(* Logix 5000 project; controller Test vendor 1 type 14 code 92 rev 33.11; software revision 33.00 *)

TASK MainTask (continuous, watchdog 500 ms) : MainProgram

MODULES
   Local : vendor 1 type 14 code 92 (ICP 0, rev 33.11)
      IN : vendor 1 type 7 code 1 (ICP 3, rev 3.2, Input RPI 20 ms)
      O : vendor 1 type 7 code 15 (ICP 2, rev 3.2, Output RPI 20 ms)
      Ethernet : 1756-ENBT (ICP 1, Ethernet 192.168.0.98, rev 6.4)
         DXM : DXM (Ethernet 192.168.0.1, rev 2.22, StandardDataDriven RPI 20 ms)
END_MODULES

TYPE Banner_IOL_Port_v4 :   // UDT that has all of the data items necessary to communicate with a specific Port on a IO-Link Master
STRUCT
   Port_Controlled : INT;   // Each bit represents a port on an IO-Link Master. Set to 1 to tell AOI to control that port.
   Port_Activate : INT;   // Each bit represents a port on an IO-Link Master. When ON that port will process any commands in queue.
   Port_Read : INT;   // Each bit represents a port on an IO-Link Master. Used to determine when device AOI has requested a Read command.
   Port_Write : INT;   // Each bit represents a port on an IO-Link Master. Used to determine when device AOI has requested a Write command.
   Port_RW_Complete : INT;   // Each bit represents a port on an IO-Link Master. Tells device AOI that Read or Write request has been completed.
   Port_Device_Read : INT;
   Data_Transfer : SINT[190];   // Array to transfer data from IO-Master to device AOIs.
END_STRUCT
END_TYPE

TYPE Banner_IOLM_EL_v4 :   // Error Log for Messages to IOLM.
STRUCT
   RW : SINT;   // 0 = Read, 1 = Write.
   Port : SINT;   // Port number that generated error.
   Index : INT;   // IO-Link Index for generated error.
END_STRUCT
END_TYPE

TYPE Banner_IOLM_v4 :   // UDT to control IO-Link Masters.
STRUCT
   Message_Source_Data : SINT[190];
   Message_Destination_Data : SINT[190];
   Error_Log : Banner_IOLM_EL_v4[10];
   Error_Write_Retry : BOOL;
   Num_Error_MSGS : DINT;
   IO_Link_Master_Busy : BOOL;   // 0 = While waiting for a command, 1 = Processing command
   AOI_Reset : BOOL;
   Port_Data : Banner_IOL_Port_v4;   // All of the necessary data to work with the various ports of the IO-Link Master.
   Halt_Operation : BOOL;   // When parameter is 1 the AOI is halted as next available time frame.
   AOI_Halted : BOOL;   // AOI is in standby mode until Halt Operation tag is set back to 0.
END_STRUCT
END_TYPE

TYPE Banner_WLF_LC25C_PDIO_v4 :   // Process data for a Banner WLS Pro unit. This includes four process data types.
STRUCT
   Segment_Mode : SINT[11];   // 0 = Off, 1 = On, 2 = Flash, 3 = Animation.
   Run_Mode : Banner_WLS_CC_v4;   // Tags for Run Mode control
   Level_Mode : INT;   // Value describing level of the device range. See Level Mode Parameter for more information.
   Dim_Blend_Mode : INT;   // Value describing the amount of blend between colors selected in Dim and Blend Mode parameter data.
   Gauge_Mode_Value : INT;   // Value describing the position of the main animation.
   LED_Mode : SINT[65];   // 0 = Off, 1 = Green, 2 = Red, 3 = Orange, 4 = Amber, 5 = Yellow, 6 = Lime Green, 7 = Spring Green, 8 = Cyan, 9 = Sky Blue, 10 = Blue, 11 = Violet, 12 = Magneta, 13 = Rose, 14 = Daylight White, 15 = Custom 1.
   Transfer_Data : SINT[32];   // Data array to send the correct state of the process data output to the IO-Link master.
END_STRUCT
END_TYPE

TYPE Banner_WLS_CC_v4 :   // Tags to control color for a WLS Pro
STRUCT
   Animation : SINT;   // 0 = Off, 1 = Steady, 2 = Flash, 3 = 2 Color Flash, 4 = 2 Color Shift, 5 = Ends Steady, 6 = Ends Flash, 7 = Scroll, 8 = Center Bounce, 9 = Bounce, 10 = Center Bounce, 11 = Intensity Sweep, 12 = 2 Color Sweep, 13 = Spectrum. WLS15 Only 14 = Level Steady, 15 = Level Flash.
   Color_1 : SINT;   // 0 = Green, 1 = Red, 2 = Orange, 3 = Amber, 4 = Yellow, 5 = Lime Green, 6 = Spring Green, 7 = Cyan, 8 = Sky Blue, 9 = Blue, 10 = Violet, 11 = Magneta, 12 = Rose, 13 = Daylight White, 14 = Custom 1, 15 = Custom 2, 16 = Incandescent, 17 = Warm White, 18 = Flourescent, 19 = Neutral White, 20 = Cool White.
   Color_1_Intensity : SINT;   // 0 = High, 1 = Low, 2 = Medium, 3 = Off, 4 = Custom.
   Speed : SINT;   // 0 = Medium, 1 = Fast, 2 = Slow, 3 = Custom.
   Pulse_Pattern : SINT;   // 0 = Normal, 1 = Strobe, 2 = Three Pulse, 3 = SOS, 4 = Random.
   Color_2 : SINT;   // 0 = Green, 1 = Red, 2 = Orange, 3 = Amber, 4 = Yellow, 5 = Lime Green, 6 = Spring Green, 7 = Cyan, 8 = Sky Blue, 9 = Blue, 10 = Violet, 11 = Magneta, 12 = Rose, 13 = Daylight White, 14 = Custom 1, 15 = Custom 2, 16 = Incandescent, 17 = Warm White, 18 = Flourescent, 19 = Neutral White, 20 = Cool White.
   Color_2_Intensity : SINT;   // 0 = High, 1 = Low, 2 = Medium, 3 = Off, 4 = Custom.
   ScrollBounce : SINT;   // 0 = Solid, 1 = Blended Tail, 2 = Center Blended.
   Percent_Width_C1 : SINT;   // 1 to 100% of Color 1.
   Direction : SINT;   // 0 = Forward, 1 = Backward.
END_STRUCT
END_TYPE

TYPE Banner_WLS_DB_Config_v4 :   // Dim and Blend Mode Config.
STRUCT
   Num_of_Colors : SINT;   // 0 = 1 Color, 1 = 2 Colors, 2 = 3 colors. Number of colors to blend in variable color mode.
   Full_Scale : INT;   // 0 to 100 = Threshold Percent
   Color_1 : SINT;   // 0 = Green, 1 = Red, 2 = Orange, 3 = Amber, 4 = Yellow, 5 = Lime Green, 6 = Spring Green, 7 = Cyan, 8 = Sky Blue, 9 = Blue, 10 = Violet, 11 = Magneta, 12 = Rose, 13 = Daylight White, 14 = Custom 1, 15 = Custom 2, 16 = Incandescent, 17 = Warm White, 18 = Flourescent, 19 = Neutral White, 20 = Cool White.
   Color_1_Intensity : SINT;   // 0 = High, 1 = Low, 2 = Medium, 3 = Off, 4 = Custom
   Color_2 : SINT;   // 0 = Green, 1 = Red, 2 = Orange, 3 = Amber, 4 = Yellow, 5 = Lime Green, 6 = Spring Green, 7 = Cyan, 8 = Sky Blue, 9 = Blue, 10 = Violet, 11 = Magneta, 12 = Rose, 13 = Daylight White, 14 = Custom 1, 15 = Custom 2, 16 = Incandescent, 17 = Warm White, 18 = Flourescent, 19 = Neutral White, 20 = Cool White.
   Color_2_Intensity : SINT;   // 0 = High, 1 = Low, 2 = Medium, 3 = Off, 4 = Custom
   Color_3 : SINT;   // 0 = Green, 1 = Red, 2 = Orange, 3 = Amber, 4 = Yellow, 5 = Lime Green, 6 = Spring Green, 7 = Cyan, 8 = Sky Blue, 9 = Blue, 10 = Violet, 11 = Magneta, 12 = Rose, 13 = Daylight White, 14 = Custom 1, 15 = Custom 2, 16 = Incandescent, 17 = Warm White, 18 = Flourescent, 19 = Neutral White, 20 = Cool White.
   Color_3_Intensity : SINT;   // 0 = High, 1 = Low, 2 = Medium, 3 = Off, 4 = Custom
   Filtering : SINT;   // 0 = None, 1 = Low, 2 = Medium, 3 = High
END_STRUCT
END_TYPE

TYPE Banner_WLS_Gauge_CC_v4 :   // Parameter Data Tags for Gauge mode color control.
STRUCT
   Threshold_Enable : SINT;   // 0 = Disabled, 1 = Enabled.
   Threshold_Value_Percent : SINT;   // 0 to 100 - Threshold %
   Threshold_Comparison : SINT;   // 0 = Less than or equal to, 1 = Greater than or equal to.
   Percent_Width_of_Main_Segment : SINT;   // 0 to 100 = Percent width of color 1
   Main_CC : Banner_WLS_CC_v4;   // Color Control for the Main Lighting.
   Back_CC : Banner_WLS_CC_v4;   // Color Control for the Background Lighting.
END_STRUCT
END_TYPE

TYPE Banner_WLS_Gauge_Config_v4 :   // Tags that control Gauge Mode.
STRUCT
   Full_Scale_Value : INT;   // 0 to 100 = Threshold Percent.
   Filtering : SINT;   // 0 = None, 1 = Low, 2 = Medium, 3 = High
   Hysteresis : SINT;   // 0 = None, 1 = Low, 2 = Medium, 3 = High
   Threshold_Markers_Type : SINT;   // 0 = Off, 1= Non-Dominant, 2= Dominant.
   CC : Banner_WLS_Gauge_CC_v4[3];   // Gauge Color Control tags.
END_STRUCT
END_TYPE

TYPE Banner_WLS_Level_Config_v4 :   // Variables that Control the Level Mode of the WLS Pro.
STRUCT
   Background_Color : SINT;   // 0 = Green, 1 = Red, 2 = Orange, 3 = Amber, 4 = Yellow, 5 = Lime Green, 6 = Spring Green, 7 = Cyan, 8 = Sky Blue, 9 = Blue, 10 = Violet, 11 = Magneta, 12 = Rose, 13 = Daylight White, 14 = Custom 1, 15 = Custom 2, 16 = Incandescent, 17 = Warm White, 18 = Flourescent, 19 = Neutral White, 20 = Cool White.
   Background_Intensity : SINT;   // 0 = High, 1 = Low, 2 = Medium, 3 = Off, 4 = Custom
   Dominance : SINT;   // 0 = Non-Dominant, 1 = Dominant
   SubSegment_Style : SINT;   // 0 = Solid, 1 = Analog
   Filtering : SINT;   // 0 = None, 1 = Low, 2 = Medium, 3 = High
   Hysteresis : SINT;   // 0 = None, 1 = Low, 2 = Medium, 3 = High
   Full_Scale_Value : INT;   // Value that controls what the full scale value is
   Threshold_Marks_Type : SINT;   // WLS15 or WLF only. 0 = Off, 1 = Non-Dominant, 2 = Dominant.
   LB_Config : Banner_WLS_CC_v4;   // Level Base Configuration
   LT_Config : Banner_WLS_LT_v4[5];   // Level Threshold Configuration
END_STRUCT
END_TYPE

TYPE Banner_WLS_LT_v4 :   // Variables to configure the Level Threshold.
STRUCT
   Threshold_Enable : SINT;   // 0 = Threshold Disabled, 1 = Threshold Enabled
   Threshold_Value : SINT;   // 0 to 100 Threshold Percent
   Threshold_Comparison : SINT;   // 0 = Less than or equal to, 1 = Greater than or equal to
   Threshold_Override : SINT;   // 0 = Override not enabled, 1 = Override enabled
   Light_Control : Banner_WLS_CC_v4;   // Color Control
END_STRUCT
END_TYPE

TYPE Banner_WLS_RD_v4 :   // UDT that stores the Read Data for a WLS Pro.
STRUCT
   Master_Cycle_Time : INT;
   Min_Cycle_Time : INT;
   M_Sequence_Capability : INT;
   IO_Link_Version_ID : INT;
   Process_Data_Input_Length : INT;
   Process_Data_Output_Length : INT;
   Combined_Vendor_ID : DINT;   // IO-Link Vendor ID
   Vendor_ID1 : INT;
   Vendor_ID2 : INT;
   Combined_Device_ID : DINT;   // IO-Link Device ID
   Device_ID1 : INT;
   Device_ID2 : INT;
   Device_ID3 : INT;
   Serial_Number : STRING;
END_STRUCT
END_TYPE

TYPE Banner_WLS_Seg_Config_v4 :   // UDT for segment setup in index 66 of the parameter data.
STRUCT
   Basic_Color : SINT;   // 0 = Green, 1 = Red, 2 = Orange, 3 = Amber, 4 = Yellow, 5 = Lime Green, 6 = Spring Green, 7 = Cyan, 8 = Sky Blue, 9 = Blue, 10 = Violet, 11 = Magneta, 12 = Rose, 13 = Daylight White, 14 = Custom 1, 15 = Custom 2, 16 = Incandescent, 17 = Warm White, 18 = Flourescent, 19 = Neutral White, 20 = Cool White.
   Basic_Flash_Rate : SINT;   // 0 = Medium, 1 = Fast, 2 = Slow, 3 = Custom.
   CC : Banner_WLS_CC_v4;   // Color Control
   Manual_Segment_Offset : SINT;   // 0 to 64 = Manual Offset in LEDs.
   Manual_Segment_Width : SINT;   // 0 to 64 = Manual width in LEDs.
END_STRUCT
END_TYPE

TYPE Banner_WLS_v4 :   // All of the parameters for a WLS Pro.
STRUCT
   Initial_Global_Read : BOOL;   // Determines if all of the IO-Link data has been read into the PLC yet
   Command : INT;   // Value placed in here will activate a read or write to a specifc IO-Link Index
   Read : Banner_WLS_RD_v4;   // Read Only Data
   Write : Banner_WLS_WD_v4;   // Write Data
   Archive : Banner_WLS_WD_v4;   // Archive of the Write Data
   Reset : BOOL;   // Resets AOI. This will force a complete parameter read of the sensor.
END_STRUCT
END_TYPE

TYPE Banner_WLS_WD_v4 :   // UDT that stores the Write Data for a WLS Pro.
STRUCT
   System_Command : INT;   // See IODD file for list of commands that can be activated via the System Command interface
   Parameter_Access_Lock : SINT;   // Write access to all parameters is prohibited while value is 1. Only this parameter can be adjusted when value is 1.
   Data_Storage_Lock : SINT;   // Automatic data storage is disabled when this value is equal to 1. Read access is not affected.
   Local_Parameterization_Lock : SINT;   // Parameterization via local control elements on device is disabled.
   Local_User_Interface_Lock : SINT;   // Operation of local user interface is disabled.
   Operating_Mode_Selection : SINT;   // 0 = Segment, 1 = Run, 2 = Level, 3 = Dim & Blend, 4 = Gauge, 5 = LED
   Segment_Mode : SINT;   // 0 = Manual Segment Config. 1 trough 10 = Number of segments in Segment Mode.
   BackGround_Color : SINT;   // 0 = Green, 1 = Red, 2 = Orange, 3 = Amber, 4 = Yellow, 5 = Lime Green, 6 = Spring Green, 7 = Cyan, 8 = Sky Blue, 9 = Blue, 10 = Violet, 11 = Magneta, 12 = Rose, 13 = Daylight White, 14 = Custom 1, 15 = Custom 2, 16 = Incandescent, 17 = Warm White, 18 = Flourescent, 19 = Neutral White, 20 = Cool White.
   Background_Intensity : SINT;   // 0 = High, 1 = Low, 2 = Medium, 3 = Off, 4 = Custom
   Animation_Sync : SINT;   // 0 = Instant Update, 1 = Synchronized Update.
   SM_Config : Banner_WLS_Seg_Config_v4[11];   // Segement Mode Configuration
   LM_Config : Banner_WLS_Level_Config_v4;   // Level Mode Configuration
   Custom_Color_1_R : INT;   // 0 to 255 for Red Custom Color 1.
   Custom_Color_1_G : INT;   // 0 to 255 for Green Custom Color 1.
   Custom_Color_1_B : INT;   // 0 to 255 for Blue Custom Color 1.
   Custom_Color_2_R : INT;   // 0 to 255 for Red Custom Color 2.
   Custom_Color_2_G : INT;   // 0 to 255 for Green Custom Color 2.
   Custom_Color_2_B : INT;   // 0 to 255 for Blue Custom Color 2.
   LED_Mode_Intensity : SINT;   // 0 = High, 1 = Low, 2 = Medium, 3 = Off, 4 = Custom
   Orientation : SINT;   // 0 = Standard, 1 = Upside Down
   Custom_Intensity : SINT;   // 0 to 100 %
   Custom_Frequency : SINT;   // 0 to 255Hz
   DB_Config : Banner_WLS_DB_Config_v4;   // Dim and Blend Configuration
   G_Config : Banner_WLS_Gauge_Config_v4;   // Gauge Configuration
   Number_of_LEDs : INT;
END_STRUCT
END_TYPE

ADD_ON_INSTRUCTION Banner_DXMR90_IOLM_v4   (* revision 4.1, vendor Banner Engineering *)
// AOI that controls a Banner IO-Link Master with Banner devices.
// Revision note:
// Revised operational order for ISDU write.
VAR_IN_OUT
   IOLM : Banner_IOLM_v4; {required}
END_VAR
VAR
   Lock : DINT; {access None}
   Byte_Length : SINT; {access None}
   Current_Port : INT; {access None}   // Current port to communicate with via the IO-Link Master.
   Timer : TIMER := (PRE := 500); {access None}
   Error_Index : DINT; {access None}
   Timer2 : TIMER := (PRE := 5000); {access None}
   Temp_Index : INT; {access None}
   ErrCount : DINT; {access None}
   Timer4 : TIMER := (PRE := 2000); {access None}
   Timer5 : TIMER := (PRE := 2000); {access None}
   Timer3 : TIMER := (PRE := 2000); {access None}
   Timer6 : TIMER := (PRE := 3000); {access None}
   Timer7 : TIMER := (PRE := 3000); {access None}
END_VAR

ROUTINE Logic   (* ladder *)
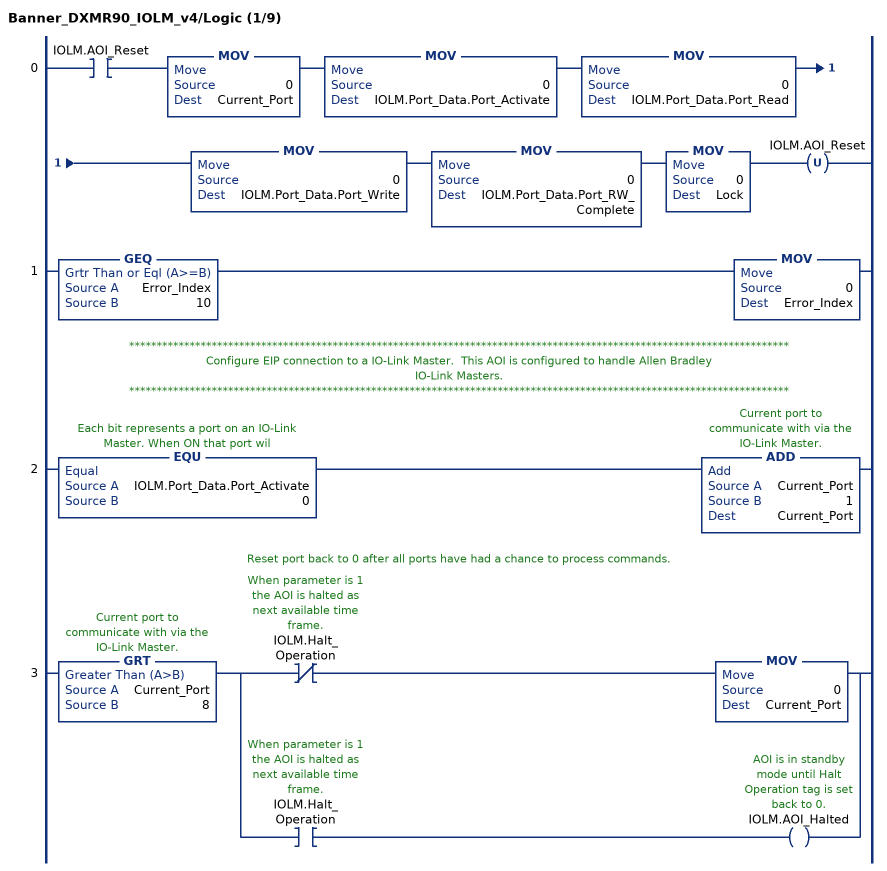
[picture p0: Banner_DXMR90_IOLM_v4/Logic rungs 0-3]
   0: XIC(IOLM.AOI_Reset)MOV(0,Current_Port)MOV(0,IOLM.Port_Data.Port_Activate)MOV(0,IOLM.Port_Data.Port_Read)MOV(0,IOLM.Port_Data.Port_Write)MOV(0,IOLM.Port_Data.Port_RW_Complete)MOV(0,Lock)OTU(IOLM.AOI_Reset);
   1: GEQ(Error_Index,10)MOV(0,Error_Index);
   // ************************************************************************************************************************
   // Configure EIP connection to a IO-Link Master.  This AOI is configured to handle Allen Bradley
   // IO-Link Masters.
   // ************************************************************************************************************************
   2: EQU(IOLM.Port_Data.Port_Activate,0)ADD(Current_Port,1,Current_Port);
   // Reset port back to 0 after all ports have had a chance to process commands.
   3: GRT(Current_Port,8)[XIO(IOLM.Halt_Operation) MOV(0,Current_Port) ,XIC(IOLM.Halt_Operation) OTE(IOLM.AOI_Halted) ];
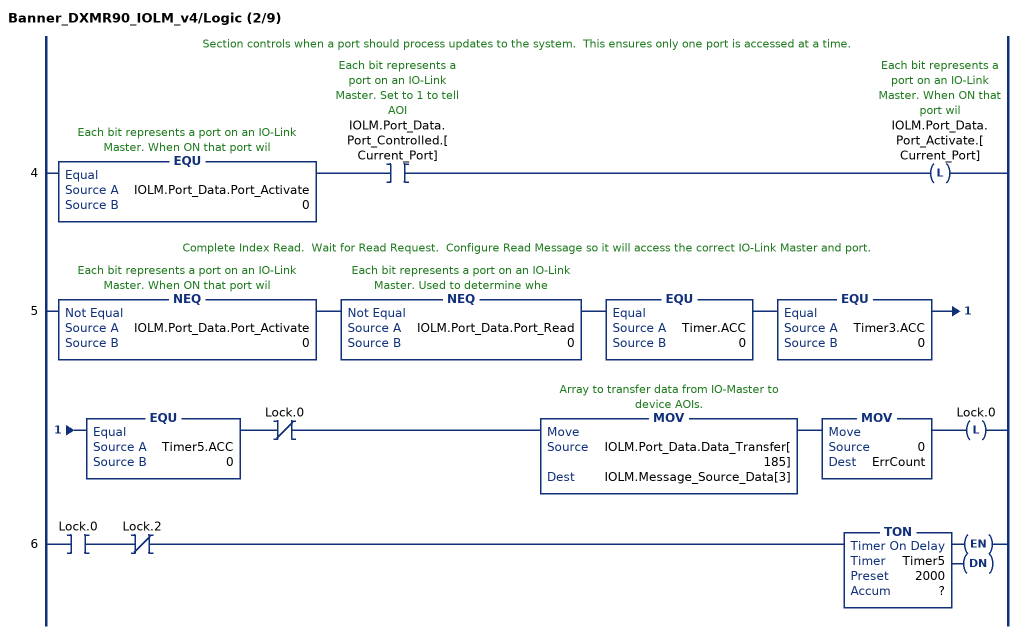
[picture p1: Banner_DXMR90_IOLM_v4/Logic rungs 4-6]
   // Section controls when a port should process updates to the system.  This ensures only one port is accessed at a time.
   4: EQU(IOLM.Port_Data.Port_Activate,0)XIC(IOLM.Port_Data.Port_Controlled.[Current_Port])OTL(IOLM.Port_Data.Port_Activate.[Current_Port]);
   // Complete Index Read.  Wait for Read Request.  Configure Read Message so it will access the correct IO-Link Master and port.
   5: NEQ(IOLM.Port_Data.Port_Activate,0)NEQ(IOLM.Port_Data.Port_Read,0)EQU(Timer.ACC,0)EQU(Timer3.ACC,0)EQU(Timer5.ACC,0)XIO(Lock.0)MOV(IOLM.Port_Data.Data_Transfer[185],IOLM.Message_Source_Data[3])MOV(0,ErrCount)OTL(Lock.0);
   6: XIC(Lock.0)XIO(Lock.2)TON(Timer5,?,?);
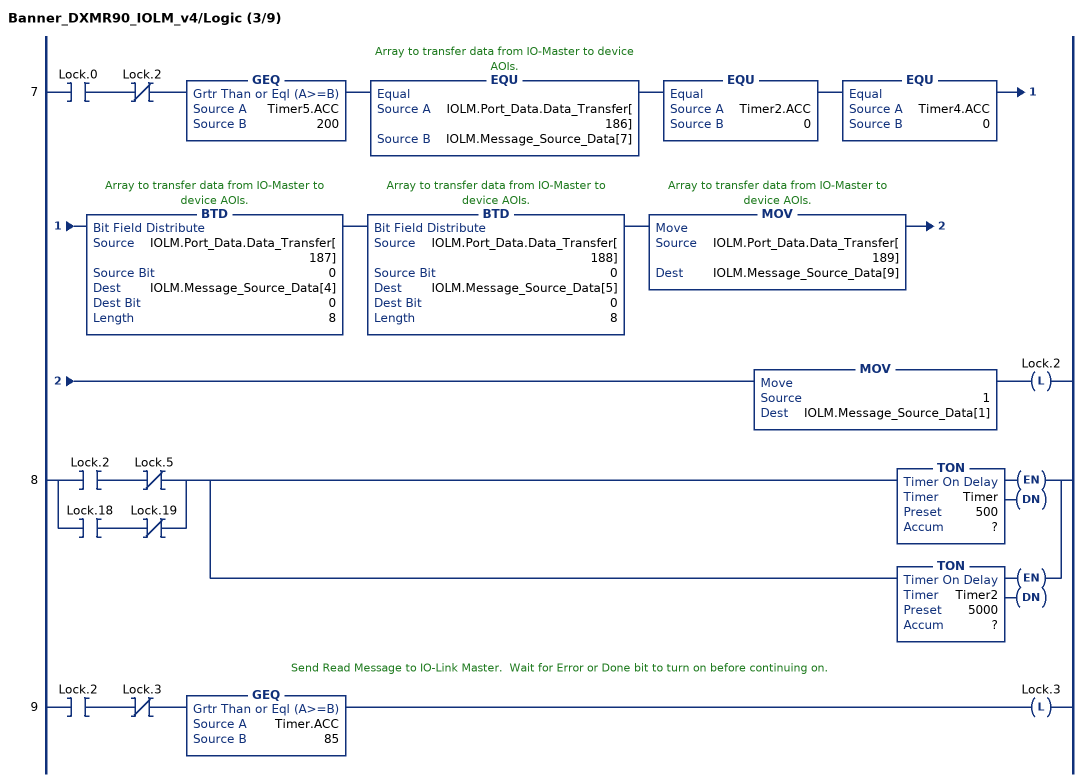
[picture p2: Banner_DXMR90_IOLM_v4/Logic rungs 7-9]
   7: XIC(Lock.0)XIO(Lock.2)GEQ(Timer5.ACC,200)EQU(IOLM.Port_Data.Data_Transfer[186],IOLM.Message_Source_Data[7])EQU(Timer2.ACC,0)EQU(Timer4.ACC,0)BTD(IOLM.Port_Data.Data_Transfer[187],0,IOLM.Message_Source_Data[4],0,8)BTD(IOLM.Port_Data.Data_Transfer[188],0,IOLM.Message_Source_Data[5],0,8)MOV(IOLM.Port_Data.Data_Transfer[189],IOLM.Message_Source_Data[9])MOV(1,IOLM.Message_Source_Data[1])OTL(Lock.2);
   8: [XIC(Lock.2) XIO(Lock.5) ,XIC(Lock.18) XIO(Lock.19) ][TON(Timer,?,?) ,TON(Timer2,?,?) ];
   // Send Read Message to IO-Link Master.  Wait for Error or Done bit to turn on before continuing on.
   9: XIC(Lock.2)XIO(Lock.3)GEQ(Timer.ACC,85)OTL(Lock.3);
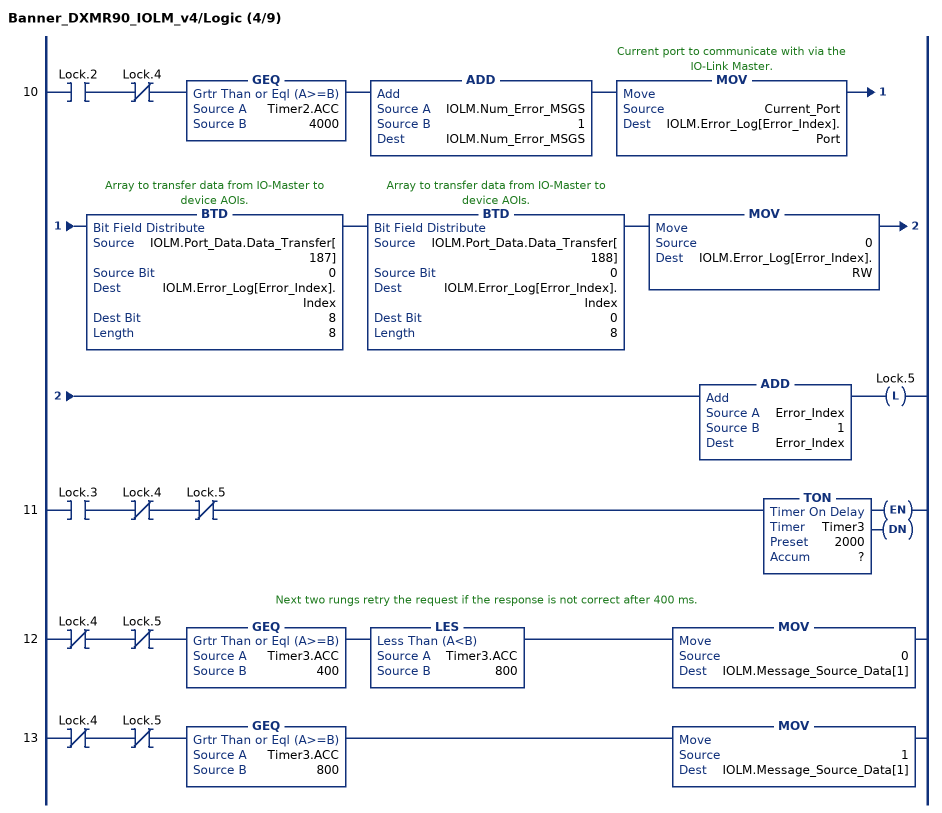
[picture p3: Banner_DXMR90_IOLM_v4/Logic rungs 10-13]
   10: XIC(Lock.2)XIO(Lock.4)GEQ(Timer2.ACC,4000)ADD(IOLM.Num_Error_MSGS,1,IOLM.Num_Error_MSGS)MOV(Current_Port,IOLM.Error_Log[Error_Index].Port)BTD(IOLM.Port_Data.Data_Transfer[187],0,IOLM.Error_Log[Error_Index].Index,8,8)BTD(IOLM.Port_Data.Data_Transfer[188],0,IOLM.Error_Log[Error_Index].Index,0,8)MOV(0,IOLM.Error_Log[Error_Index].RW)ADD(Error_Index,1,Error_Index)OTL(Lock.5);
   11: XIC(Lock.3)XIO(Lock.4)XIO(Lock.5)TON(Timer3,?,?);
   // Next two rungs retry the request if the response is not correct after 400 ms.
   12: XIO(Lock.4)XIO(Lock.5)GEQ(Timer3.ACC,400)LES(Timer3.ACC,800)MOV(0,IOLM.Message_Source_Data[1]);
   13: XIO(Lock.4)XIO(Lock.5)GEQ(Timer3.ACC,800)MOV(1,IOLM.Message_Source_Data[1]);
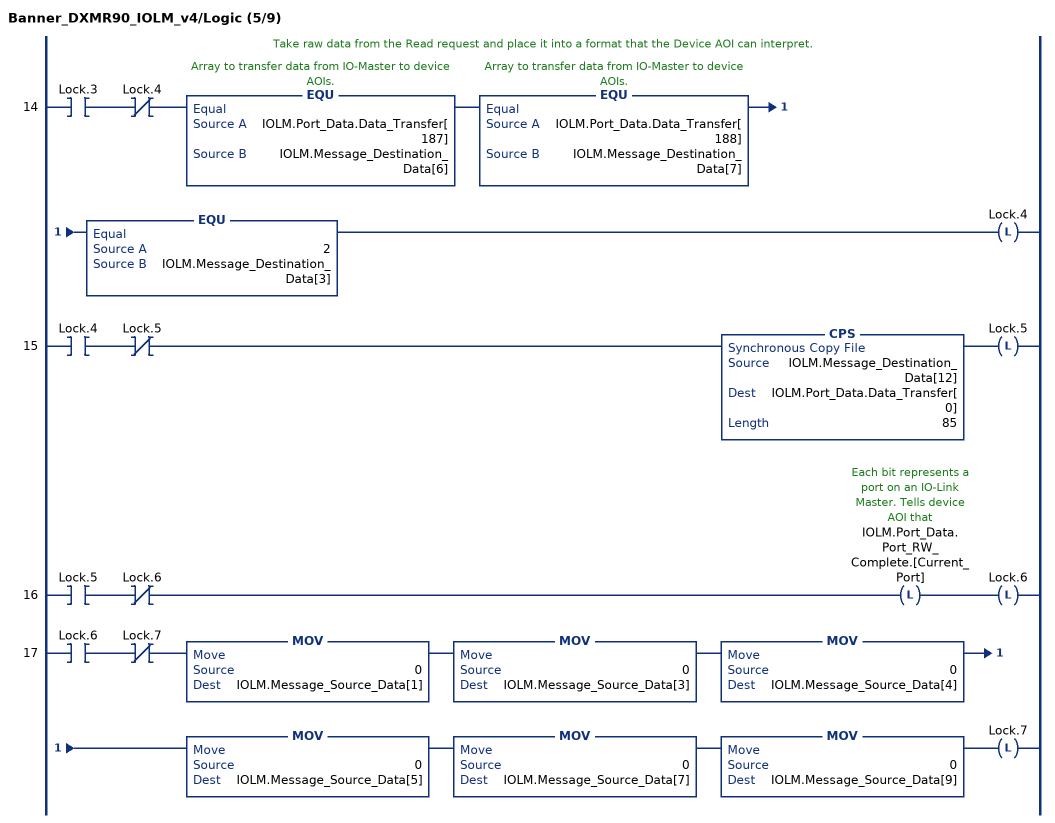
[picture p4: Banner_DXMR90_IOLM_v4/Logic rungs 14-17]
   // Take raw data from the Read request and place it into a format that the Device AOI can interpret.
   14: XIC(Lock.3)XIO(Lock.4)EQU(IOLM.Port_Data.Data_Transfer[187],IOLM.Message_Destination_Data[6])EQU(IOLM.Port_Data.Data_Transfer[188],IOLM.Message_Destination_Data[7])EQU(2,IOLM.Message_Destination_Data[3])OTL(Lock.4);
   15: XIC(Lock.4)XIO(Lock.5)CPS(IOLM.Message_Destination_Data[12],IOLM.Port_Data.Data_Transfer[0],85)OTL(Lock.5);
   16: XIC(Lock.5)XIO(Lock.6)OTL(IOLM.Port_Data.Port_RW_Complete.[Current_Port])OTL(Lock.6);
   17: XIC(Lock.6)XIO(Lock.7)MOV(0,IOLM.Message_Source_Data[1])MOV(0,IOLM.Message_Source_Data[3])MOV(0,IOLM.Message_Source_Data[4])MOV(0,IOLM.Message_Source_Data[5])MOV(0,IOLM.Message_Source_Data[7])MOV(0,IOLM.Message_Source_Data[9])OTL(Lock.7);
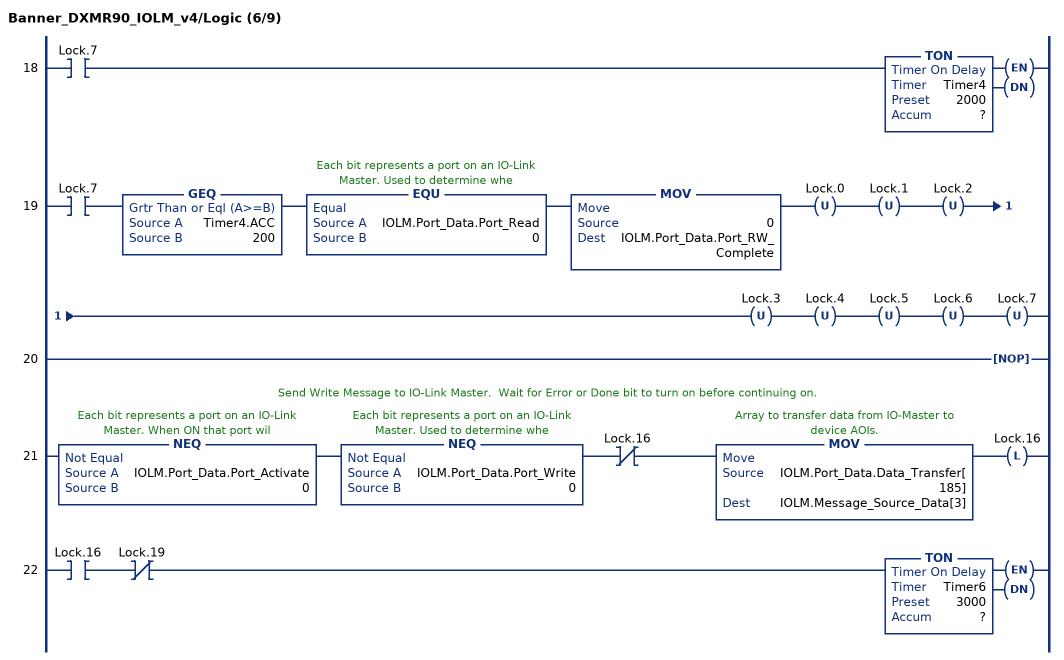
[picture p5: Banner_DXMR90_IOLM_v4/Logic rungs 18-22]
   18: XIC(Lock.7)TON(Timer4,?,?);
   19: XIC(Lock.7)GEQ(Timer4.ACC,200)EQU(IOLM.Port_Data.Port_Read,0)MOV(0,IOLM.Port_Data.Port_RW_Complete)OTU(Lock.0)OTU(Lock.1)OTU(Lock.2)OTU(Lock.3)OTU(Lock.4)OTU(Lock.5)OTU(Lock.6)OTU(Lock.7);
   20: NOP();
   // Send Write Message to IO-Link Master.  Wait for Error or Done bit to turn on before continuing on.
   21: NEQ(IOLM.Port_Data.Port_Activate,0)NEQ(IOLM.Port_Data.Port_Write,0)XIO(Lock.16)MOV(IOLM.Port_Data.Data_Transfer[185],IOLM.Message_Source_Data[3])OTL(Lock.16);
   22: XIC(Lock.16)XIO(Lock.19)TON(Timer6,?,?);
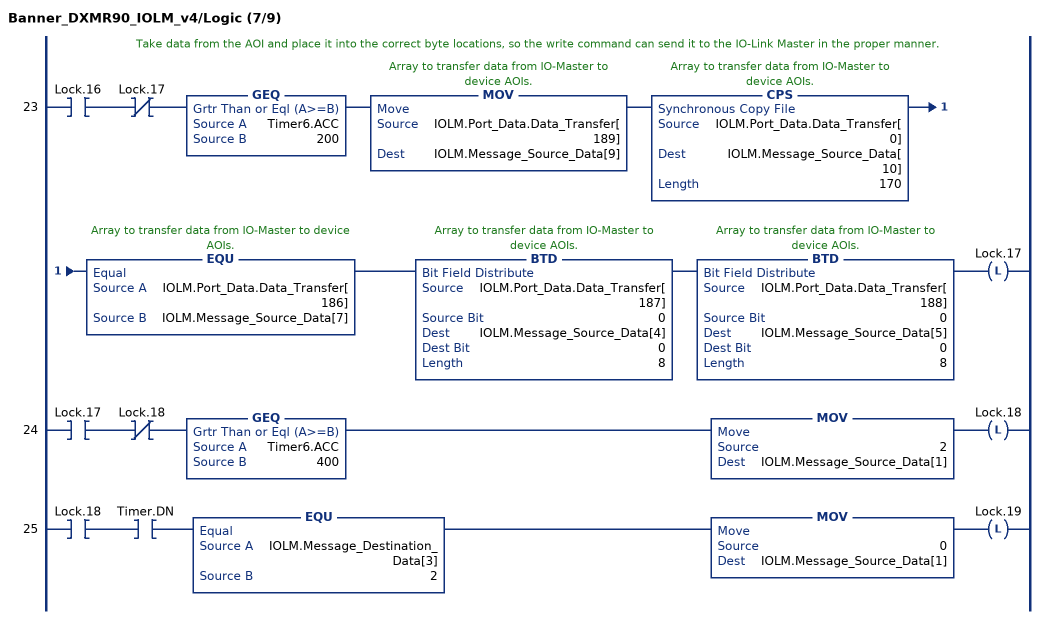
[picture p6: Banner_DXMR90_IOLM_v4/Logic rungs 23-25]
   // Take data from the AOI and place it into the correct byte locations, so the write command can send it to the IO-Link Master in the proper manner.
   23: XIC(Lock.16)XIO(Lock.17)GEQ(Timer6.ACC,200)MOV(IOLM.Port_Data.Data_Transfer[189],IOLM.Message_Source_Data[9])CPS(IOLM.Port_Data.Data_Transfer[0],IOLM.Message_Source_Data[10],170)EQU(IOLM.Port_Data.Data_Transfer[186],IOLM.Message_Source_Data[7])BTD(IOLM.Port_Data.Data_Transfer[187],0,IOLM.Message_Source_Data[4],0,8)BTD(IOLM.Port_Data.Data_Transfer[188],0,IOLM.Message_Source_Data[5],0,8)OTL(Lock.17);
   24: XIC(Lock.17)XIO(Lock.18)GEQ(Timer6.ACC,400)MOV(2,IOLM.Message_Source_Data[1])OTL(Lock.18);
   25: XIC(Lock.18)XIC(Timer.DN)EQU(IOLM.Message_Destination_Data[3],2)MOV(0,IOLM.Message_Source_Data[1])OTL(Lock.19);
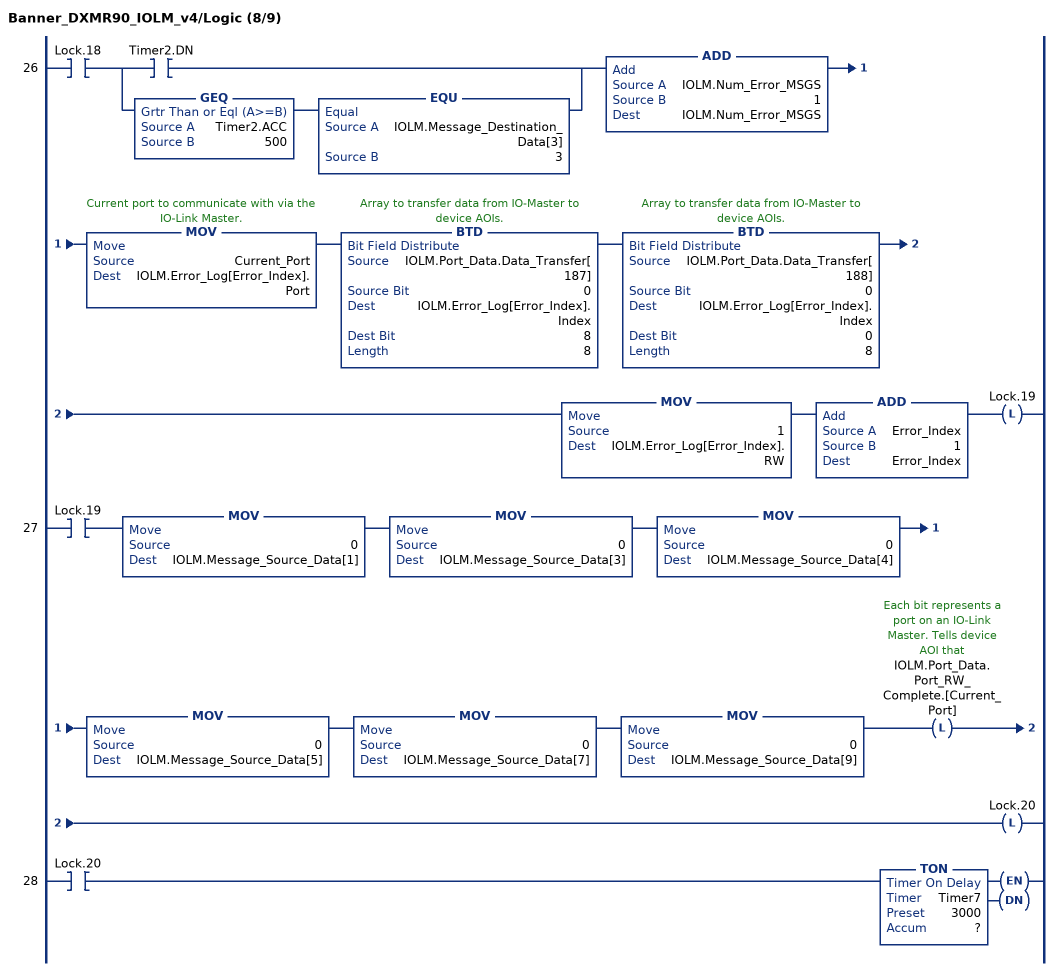
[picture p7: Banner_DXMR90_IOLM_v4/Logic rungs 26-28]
   26: XIC(Lock.18)[XIC(Timer2.DN) ,GEQ(Timer2.ACC,500) EQU(IOLM.Message_Destination_Data[3],3) ]ADD(IOLM.Num_Error_MSGS,1,IOLM.Num_Error_MSGS)MOV(Current_Port,IOLM.Error_Log[Error_Index].Port)BTD(IOLM.Port_Data.Data_Transfer[187],0,IOLM.Error_Log[Error_Index].Index,8,8)BTD(IOLM.Port_Data.Data_Transfer[188],0,IOLM.Error_Log[Error_Index].Index,0,8)MOV(1,IOLM.Error_Log[Error_Index].RW)ADD(Error_Index,1,Error_Index)OTL(Lock.19);
   27: XIC(Lock.19)MOV(0,IOLM.Message_Source_Data[1])MOV(0,IOLM.Message_Source_Data[3])MOV(0,IOLM.Message_Source_Data[4])MOV(0,IOLM.Message_Source_Data[5])MOV(0,IOLM.Message_Source_Data[7])MOV(0,IOLM.Message_Source_Data[9])OTL(IOLM.Port_Data.Port_RW_Complete.[Current_Port])OTL(Lock.20);
   28: XIC(Lock.20)TON(Timer7,?,?);
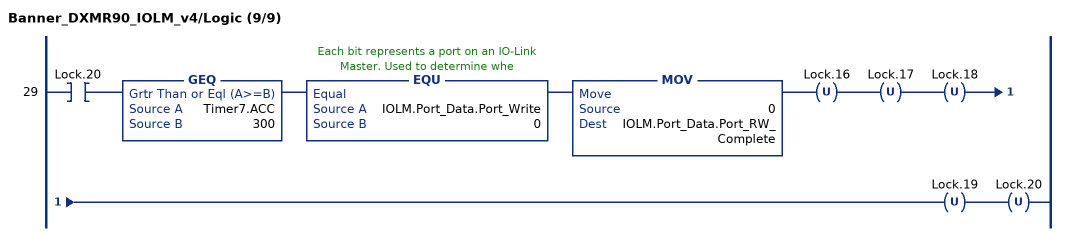
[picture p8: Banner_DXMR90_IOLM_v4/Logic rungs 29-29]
   29: XIC(Lock.20)GEQ(Timer7.ACC,300)EQU(IOLM.Port_Data.Port_Write,0)MOV(0,IOLM.Port_Data.Port_RW_Complete)OTU(Lock.16)OTU(Lock.17)OTU(Lock.18)OTU(Lock.19)OTU(Lock.20);
END_ROUTINE
END_ADD_ON_INSTRUCTION

ADD_ON_INSTRUCTION Banner_WLF_LC25C_PD_v4   (* revision 4.0, vendor Banner Engineering *)
// Takes the raw SINT information and converts that data into actual information. Uses WLF12 and LC25.
VAR_IN_OUT
   PD : Banner_WLF_LC25C_PDIO_v4; {required}
END_VAR
VAR_INPUT
   Byte_Swap : BOOL; {required}   // Swap the LSB and the MSB with each other.
   Operation_Mode : INT; {required}   // 0= Segment, 1 = Run, 2 = Level, 3 = Variable Color, 4 = Position, 5 = LED
END_VAR
VAR
   Data_Byte : SINT[72]; {access None}
   Temp_Data : SINT[64]; {access None}
   Index2 : DINT; {access None}
   Index1 : DINT; {access None}
   Control : DINT; {access None}
END_VAR

ROUTINE Logic   (* ladder *)
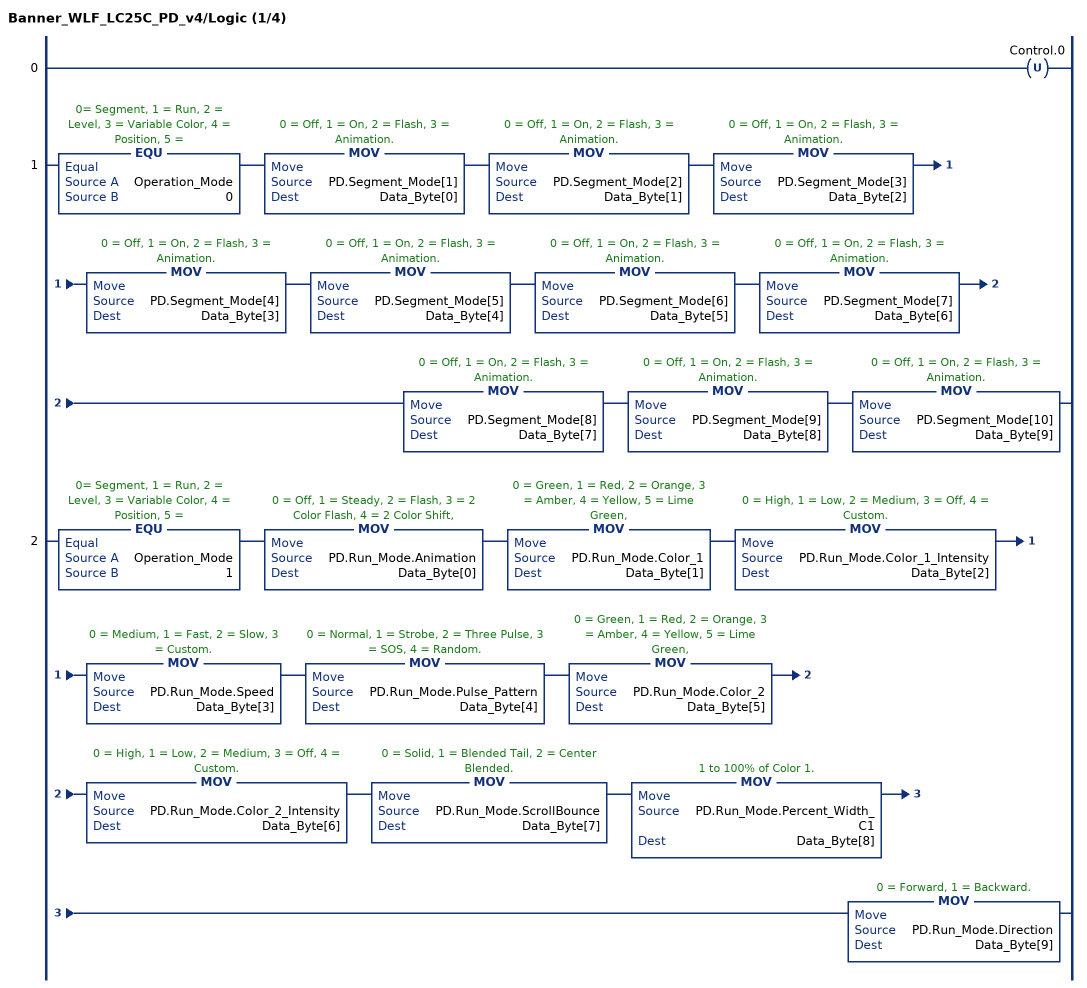
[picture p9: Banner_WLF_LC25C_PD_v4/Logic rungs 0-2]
   0: OTU(Control.0);
   1: EQU(Operation_Mode,0)MOV(PD.Segment_Mode[1],Data_Byte[0])MOV(PD.Segment_Mode[2],Data_Byte[1])MOV(PD.Segment_Mode[3],Data_Byte[2])MOV(PD.Segment_Mode[4],Data_Byte[3])MOV(PD.Segment_Mode[5],Data_Byte[4])MOV(PD.Segment_Mode[6],Data_Byte[5])MOV(PD.Segment_Mode[7],Data_Byte[6])MOV(PD.Segment_Mode[8],Data_Byte[7])MOV(PD.Segment_Mode[9],Data_Byte[8])MOV(PD.Segment_Mode[10],Data_Byte[9]);
   2: EQU(Operation_Mode,1)MOV(PD.Run_Mode.Animation,Data_Byte[0])MOV(PD.Run_Mode.Color_1,Data_Byte[1])MOV(PD.Run_Mode.Color_1_Intensity,Data_Byte[2])MOV(PD.Run_Mode.Speed,Data_Byte[3])MOV(PD.Run_Mode.Pulse_Pattern,Data_Byte[4])MOV(PD.Run_Mode.Color_2,Data_Byte[5])MOV(PD.Run_Mode.Color_2_Intensity,Data_Byte[6])MOV(PD.Run_Mode.ScrollBounce,Data_Byte[7])MOV(PD.Run_Mode.Percent_Width_C1,Data_Byte[8])MOV(PD.Run_Mode.Direction,Data_Byte[9]);
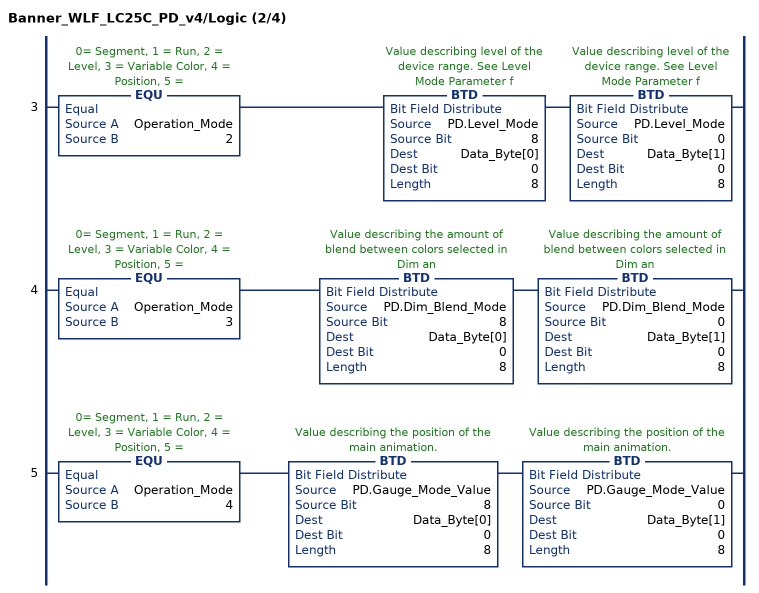
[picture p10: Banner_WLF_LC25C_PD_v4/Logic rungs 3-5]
   3: EQU(Operation_Mode,2)BTD(PD.Level_Mode,8,Data_Byte[0],0,8)BTD(PD.Level_Mode,0,Data_Byte[1],0,8);
   4: EQU(Operation_Mode,3)BTD(PD.Dim_Blend_Mode,8,Data_Byte[0],0,8)BTD(PD.Dim_Blend_Mode,0,Data_Byte[1],0,8);
   5: EQU(Operation_Mode,4)BTD(PD.Gauge_Mode_Value,8,Data_Byte[0],0,8)BTD(PD.Gauge_Mode_Value,0,Data_Byte[1],0,8);
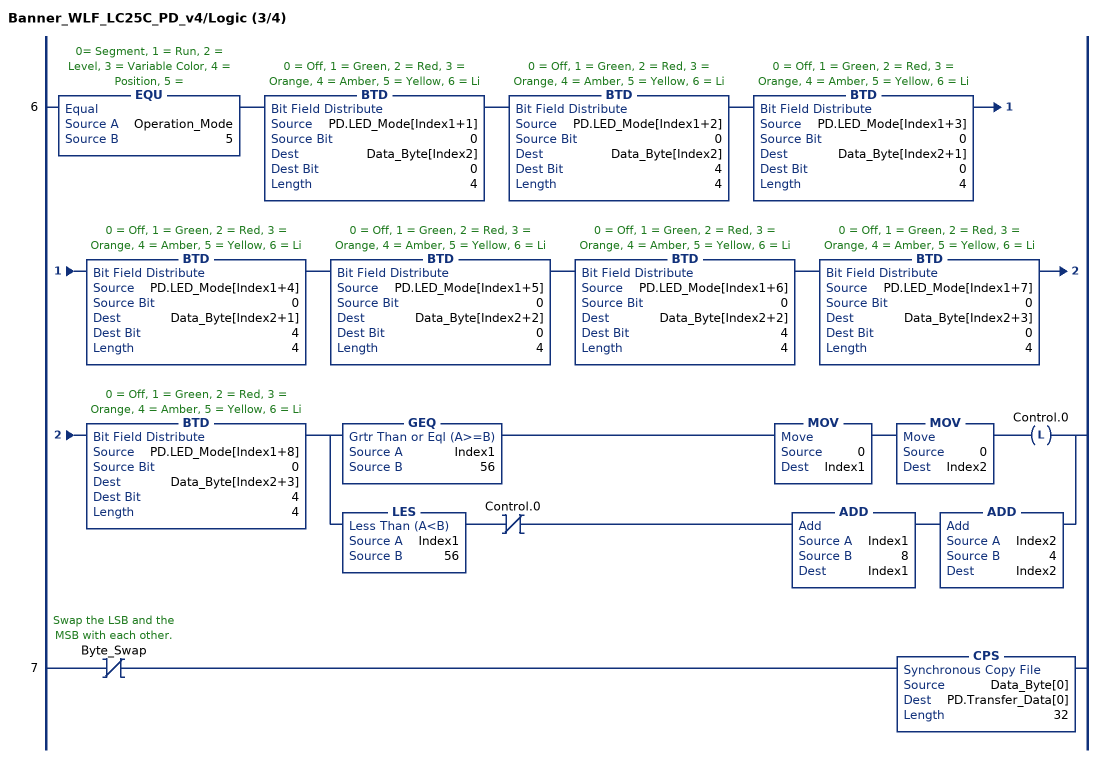
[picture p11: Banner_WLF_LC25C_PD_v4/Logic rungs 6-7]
   6: EQU(Operation_Mode,5)BTD(PD.LED_Mode[Index1+1],0,Data_Byte[Index2],0,4)BTD(PD.LED_Mode[Index1+2],0,Data_Byte[Index2],4,4)BTD(PD.LED_Mode[Index1+3],0,Data_Byte[Index2+1],0,4)BTD(PD.LED_Mode[Index1+4],0,Data_Byte[Index2+1],4,4)BTD(PD.LED_Mode[Index1+5],0,Data_Byte[Index2+2],0,4)BTD(PD.LED_Mode[Index1+6],0,Data_Byte[Index2+2],4,4)BTD(PD.LED_Mode[Index1+7],0,Data_Byte[Index2+3],0,4)BTD(PD.LED_Mode[Index1+8],0,Data_Byte[Index2+3],4,4)[GEQ(Index1,56) MOV(0,Index1) MOV(0,Index2) OTL(Control.0) ,LES(Index1,56) XIO(Control.0) ADD(Index1,8,Index1) ADD(Index2,4,Index2) ];
   7: XIO(Byte_Swap)CPS(Data_Byte[0],PD.Transfer_Data[0],32);
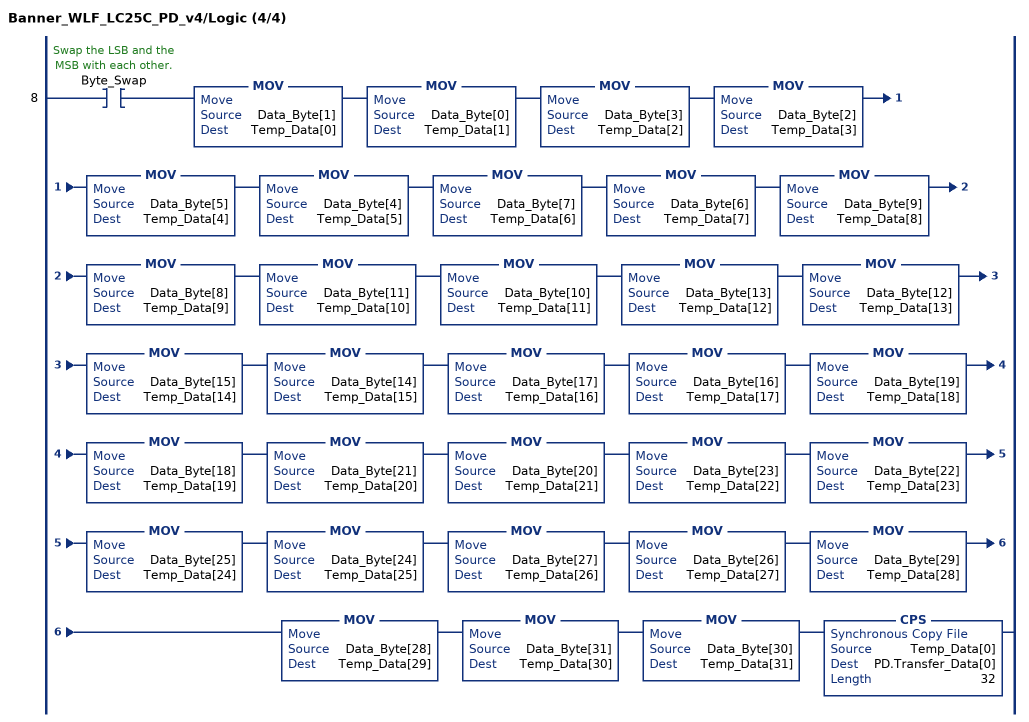
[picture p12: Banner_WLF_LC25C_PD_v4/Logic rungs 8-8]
   8: XIC(Byte_Swap)MOV(Data_Byte[1],Temp_Data[0])MOV(Data_Byte[0],Temp_Data[1])MOV(Data_Byte[3],Temp_Data[2])MOV(Data_Byte[2],Temp_Data[3])MOV(Data_Byte[5],Temp_Data[4])MOV(Data_Byte[4],Temp_Data[5])MOV(Data_Byte[7],Temp_Data[6])MOV(Data_Byte[6],Temp_Data[7])MOV(Data_Byte[9],Temp_Data[8])MOV(Data_Byte[8],Temp_Data[9])MOV(Data_Byte[11],Temp_Data[10])MOV(Data_Byte[10],Temp_Data[11])MOV(Data_Byte[13],Temp_Data[12])MOV(Data_Byte[12],Temp_Data[13])MOV(Data_Byte[15],Temp_Data[14])MOV(Data_Byte[14],Temp_Data[15])MOV(Data_Byte[17],Temp_Data[16])MOV(Data_Byte[16],Temp_Data[17])MOV(Data_Byte[19],Temp_Data[18])MOV(Data_Byte[18],Temp_Data[19])MOV(Data_Byte[21],Temp_Data[20])MOV(Data_Byte[20],Temp_Data[21])MOV(Data_Byte[23],Temp_Data[22])MOV(Data_Byte[22],Temp_Data[23])MOV(Data_Byte[25],Temp_Data[24])MOV(Data_Byte[24],Temp_Data[25])MOV(Data_Byte[27],Temp_Data[26])MOV(Data_Byte[26],Temp_Data[27])MOV(Data_Byte[29],Temp_Data[28])MOV(Data_Byte[28],Temp_Data[29])MOV(Data_Byte[31],Temp_Data[30])MOV(Data_Byte[30],Temp_Data[31])CPS(Temp_Data[0],PD.Transfer_Data[0],32);
END_ROUTINE
END_ADD_ON_INSTRUCTION

ADD_ON_INSTRUCTION Banner_WLS_Param_v4   (* revision 4.2, vendor Banner Engineering *)
// AOI to read and write parameter data to an IO-Link WLS Pro.
// Revision note:
// Updated for WLF lights.
VAR_IN_OUT
   WLS : Banner_WLS_v4; {required}
   Port_Data : Banner_IOL_Port_v4; {required}
END_VAR
VAR_INPUT
   Port : INT; {required}   // Port Number that device is plugged into.
   Type : SINT; {required}   // 0 = WLS27, 1 = WLS15, 2 = WLF
END_VAR
VAR
   Local_Control : DINT; {access None}
   Global_Read_Command_Value : INT; {access None}
   Global_Write_Command_Value : INT; {access None}
   Command_Being_Processed : BOOL; {access None}
   Update_Archive : BOOL; {access None}
   Index_Write_Inprocess : DINT; {access None}
   Index_Write_Control : DINT; {access None}
   Inprocess_Index : DINT; {access None}
   IndexR : DINT; {access None}   // Index keeping track of Reads in an array.
   S_Index : DINT; {access None}
   IndexW : DINT; {access None}   // Index keeping track of Writes in an array.
   SW_Index : DINT; {access None}
   Index_Segment_Read : DINT; {access None}
   LT_Index : DINT; {access None}
   IndexW2 : DINT; {access None}
   LTW_Index : DINT; {access None}
   G_Index : DINT; {access None}
   IndexW3 : DINT; {access None}
   GW_Index : DINT; {access None}
END_VAR

ROUTINE Logic   (* ladder *)
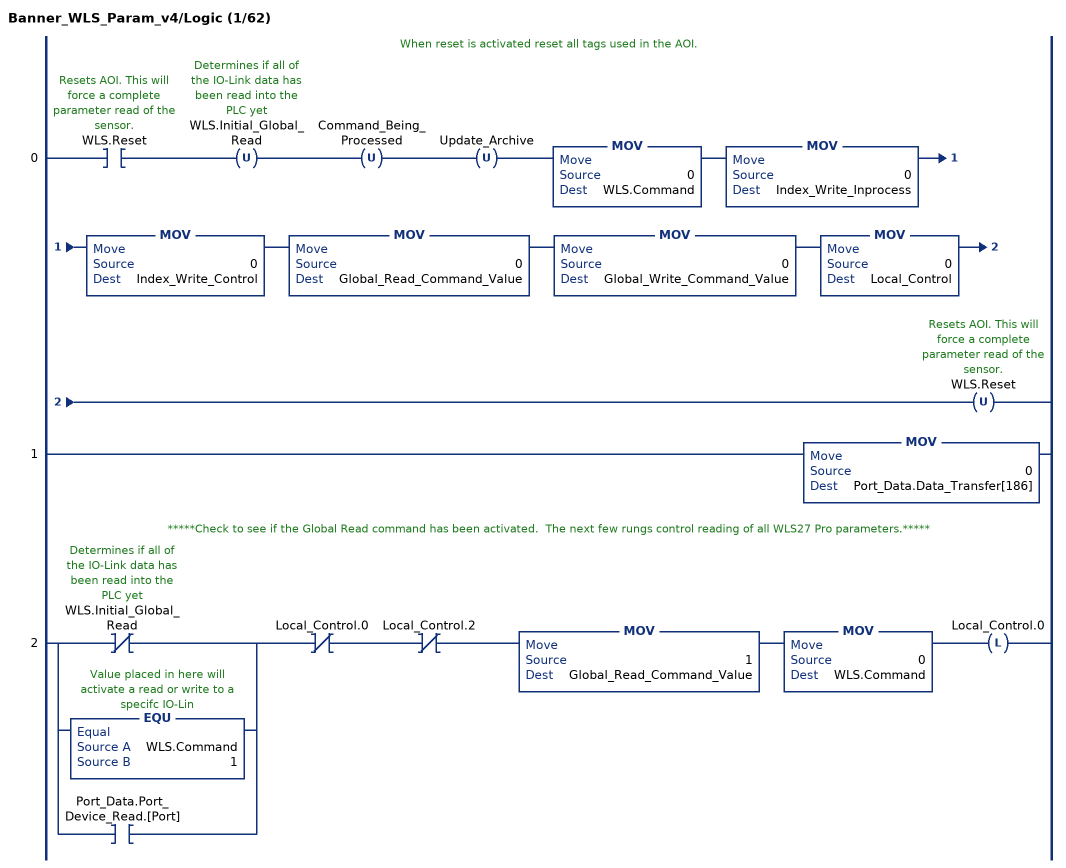
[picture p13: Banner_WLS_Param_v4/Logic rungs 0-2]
   // When reset is activated reset all tags used in the AOI.
   0: XIC(WLS.Reset)OTU(WLS.Initial_Global_Read)OTU(Command_Being_Processed)OTU(Update_Archive)MOV(0,WLS.Command)MOV(0,Index_Write_Inprocess)MOV(0,Index_Write_Control)MOV(0,Global_Read_Command_Value)MOV(0,Global_Write_Command_Value)MOV(0,Local_Control)OTU(WLS.Reset);
   1: MOV(0,Port_Data.Data_Transfer[186]);
   // *****Check to see if the Global Read command has been activated.  The next few rungs control reading of all WLS27 Pro parameters.*****
   2: [XIO(WLS.Initial_Global_Read) ,EQU(WLS.Command,1) ,XIC(Port_Data.Port_Device_Read.[Port]) ]XIO(Local_Control.0)XIO(Local_Control.2)MOV(1,Global_Read_Command_Value)MOV(0,WLS.Command)OTL(Local_Control.0);
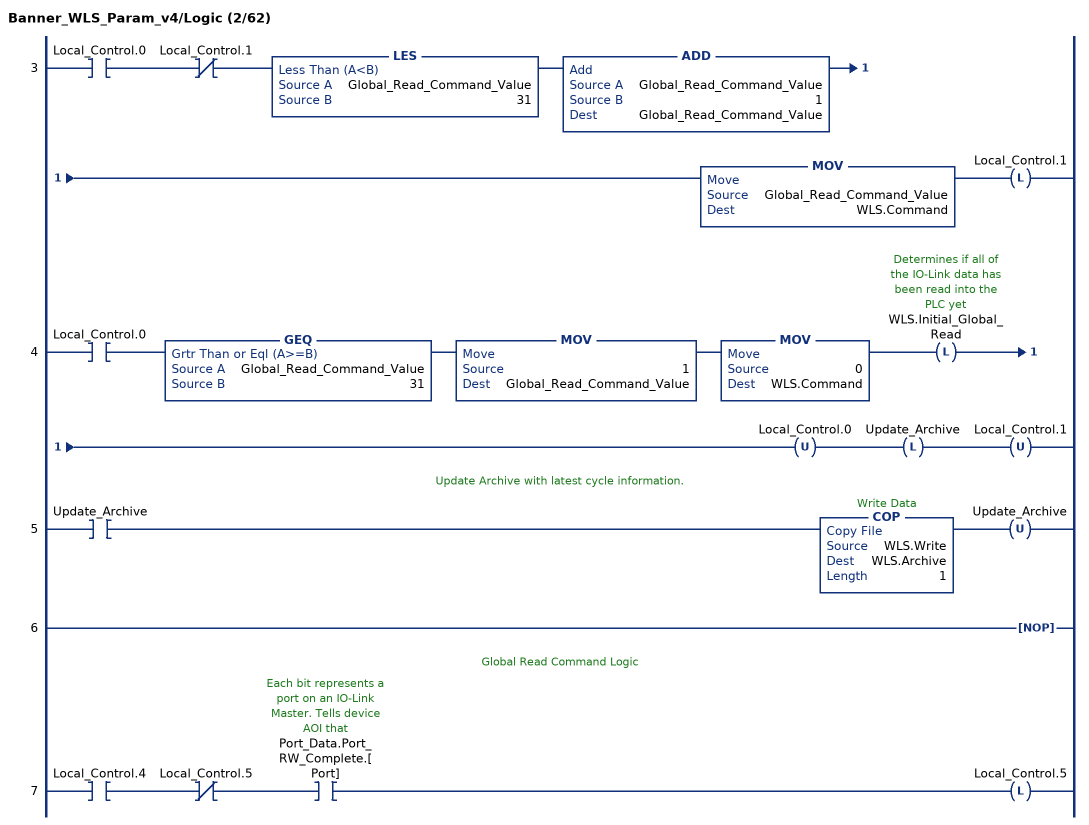
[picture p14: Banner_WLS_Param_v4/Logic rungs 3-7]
   3: XIC(Local_Control.0)XIO(Local_Control.1)LES(Global_Read_Command_Value,31)ADD(Global_Read_Command_Value,1,Global_Read_Command_Value)MOV(Global_Read_Command_Value,WLS.Command)OTL(Local_Control.1);
   4: XIC(Local_Control.0)GEQ(Global_Read_Command_Value,31)MOV(1,Global_Read_Command_Value)MOV(0,WLS.Command)OTL(WLS.Initial_Global_Read)OTU(Local_Control.0)OTL(Update_Archive)OTU(Local_Control.1);
   // Update Archive with latest cycle information.
   5: XIC(Update_Archive)COP(WLS.Write,WLS.Archive,1)OTU(Update_Archive);
   6: NOP();
   // Global Read Command Logic
   7: XIC(Local_Control.4)XIO(Local_Control.5)XIC(Port_Data.Port_RW_Complete.[Port])OTL(Local_Control.5);
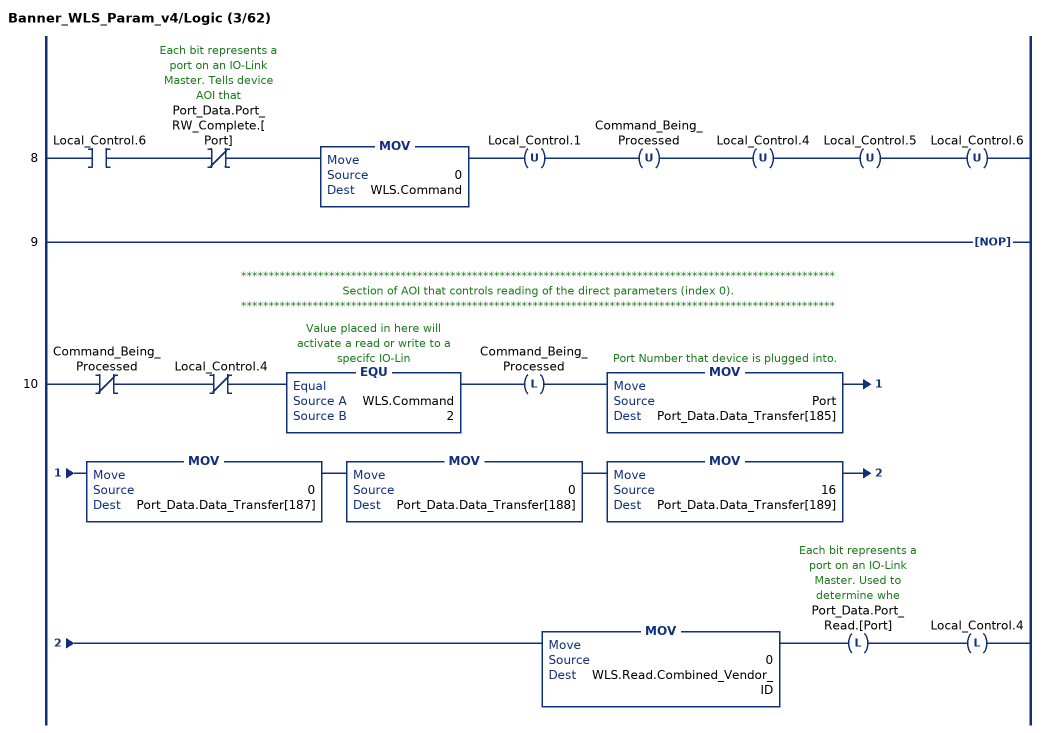
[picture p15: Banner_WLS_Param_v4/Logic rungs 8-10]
   8: XIC(Local_Control.6)XIO(Port_Data.Port_RW_Complete.[Port])MOV(0,WLS.Command)OTU(Local_Control.1)OTU(Command_Being_Processed)OTU(Local_Control.4)OTU(Local_Control.5)OTU(Local_Control.6);
   9: NOP();
   // ************************************************************************************************************
   // Section of AOI that controls reading of the direct parameters (index 0).
   // ************************************************************************************************************
   10: XIO(Command_Being_Processed)XIO(Local_Control.4)EQU(WLS.Command,2)OTL(Command_Being_Processed)MOV(Port,Port_Data.Data_Transfer[185])MOV(0,Port_Data.Data_Transfer[187])MOV(0,Port_Data.Data_Transfer[188])MOV(16,Port_Data.Data_Transfer[189])MOV(0,WLS.Read.Combined_Vendor_ID)OTL(Port_Data.Port_Read.[Port])OTL(Local_Control.4);
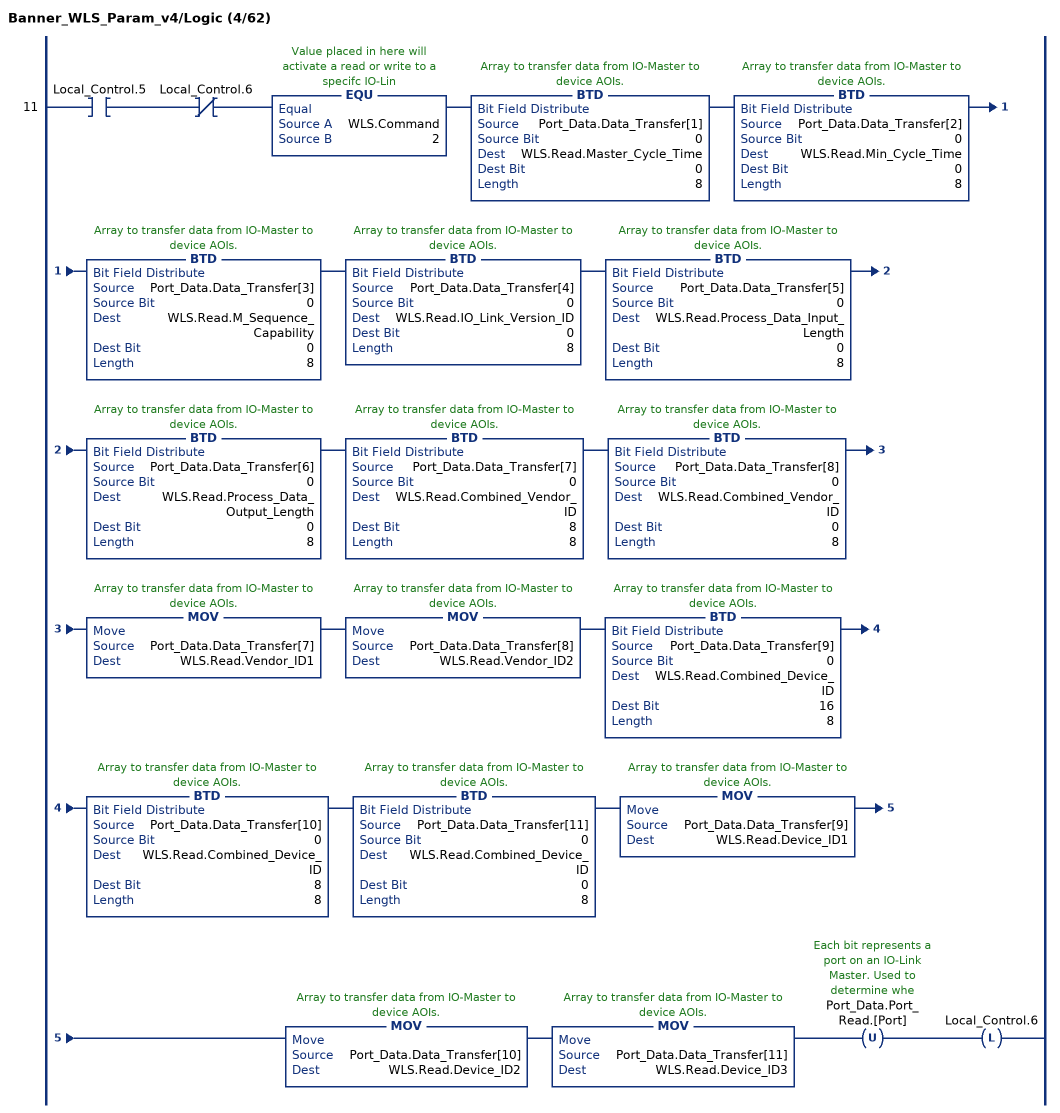
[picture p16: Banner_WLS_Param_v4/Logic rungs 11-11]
   11: XIC(Local_Control.5)XIO(Local_Control.6)EQU(WLS.Command,2)BTD(Port_Data.Data_Transfer[1],0,WLS.Read.Master_Cycle_Time,0,8)BTD(Port_Data.Data_Transfer[2],0,WLS.Read.Min_Cycle_Time,0,8)BTD(Port_Data.Data_Transfer[3],0,WLS.Read.M_Sequence_Capability,0,8)BTD(Port_Data.Data_Transfer[4],0,WLS.Read.IO_Link_Version_ID,0,8)BTD(Port_Data.Data_Transfer[5],0,WLS.Read.Process_Data_Input_Length,0,8)BTD(Port_Data.Data_Transfer[6],0,WLS.Read.Process_Data_Output_Length,0,8)BTD(Port_Data.Data_Transfer[7],0,WLS.Read.Combined_Vendor_ID,8,8)BTD(Port_Data.Data_Transfer[8],0,WLS.Read.Combined_Vendor_ID,0,8)MOV(Port_Data.Data_Transfer[7],WLS.Read.Vendor_ID1)MOV(Port_Data.Data_Transfer[8],WLS.Read.Vendor_ID2)BTD(Port_Data.Data_Transfer[9],0,WLS.Read.Combined_Device_ID,16,8)BTD(Port_Data.Data_Transfer[10],0,WLS.Read.Combined_Device_ID,8,8)BTD(Port_Data.Data_Transfer[11],0,WLS.Read.Combined_Device_ID,0,8)MOV(Port_Data.Data_Transfer[9],WLS.Read.Device_ID1)MOV(Port_Data.Data_Transfer[10],WLS.Read.Device_ID2)MOV(Port_Data.Data_Transfer[11],WLS.Read.Device_ID3)OTU(Port_Data.Port_Read.[Port])OTL(Local_Control.6);
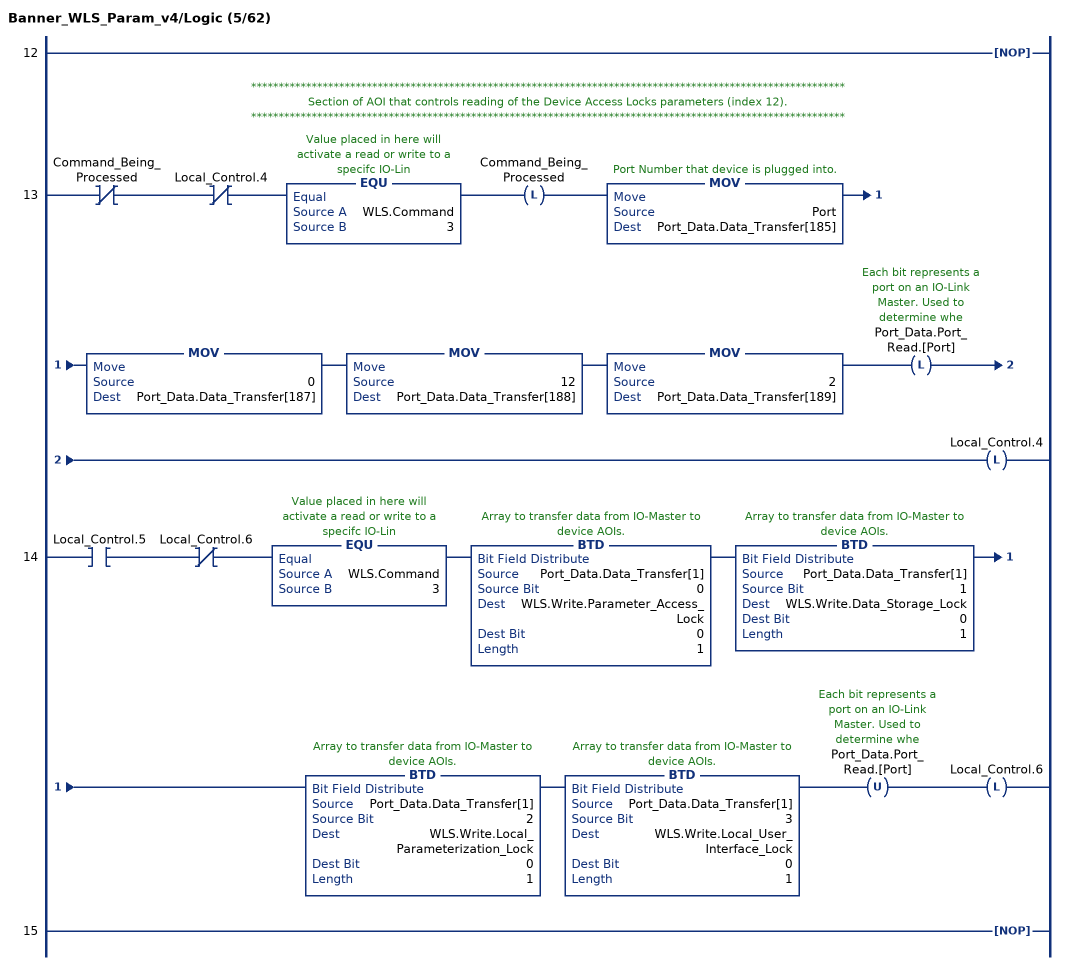
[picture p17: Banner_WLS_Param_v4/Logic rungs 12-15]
   12: NOP();
   // ************************************************************************************************************
   // Section of AOI that controls reading of the Device Access Locks parameters (index 12).
   // ************************************************************************************************************
   13: XIO(Command_Being_Processed)XIO(Local_Control.4)EQU(WLS.Command,3)OTL(Command_Being_Processed)MOV(Port,Port_Data.Data_Transfer[185])MOV(0,Port_Data.Data_Transfer[187])MOV(12,Port_Data.Data_Transfer[188])MOV(2,Port_Data.Data_Transfer[189])OTL(Port_Data.Port_Read.[Port])OTL(Local_Control.4);
   14: XIC(Local_Control.5)XIO(Local_Control.6)EQU(WLS.Command,3)BTD(Port_Data.Data_Transfer[1],0,WLS.Write.Parameter_Access_Lock,0,1)BTD(Port_Data.Data_Transfer[1],1,WLS.Write.Data_Storage_Lock,0,1)BTD(Port_Data.Data_Transfer[1],2,WLS.Write.Local_Parameterization_Lock,0,1)BTD(Port_Data.Data_Transfer[1],3,WLS.Write.Local_User_Interface_Lock,0,1)OTU(Port_Data.Port_Read.[Port])OTL(Local_Control.6);
   15: NOP();
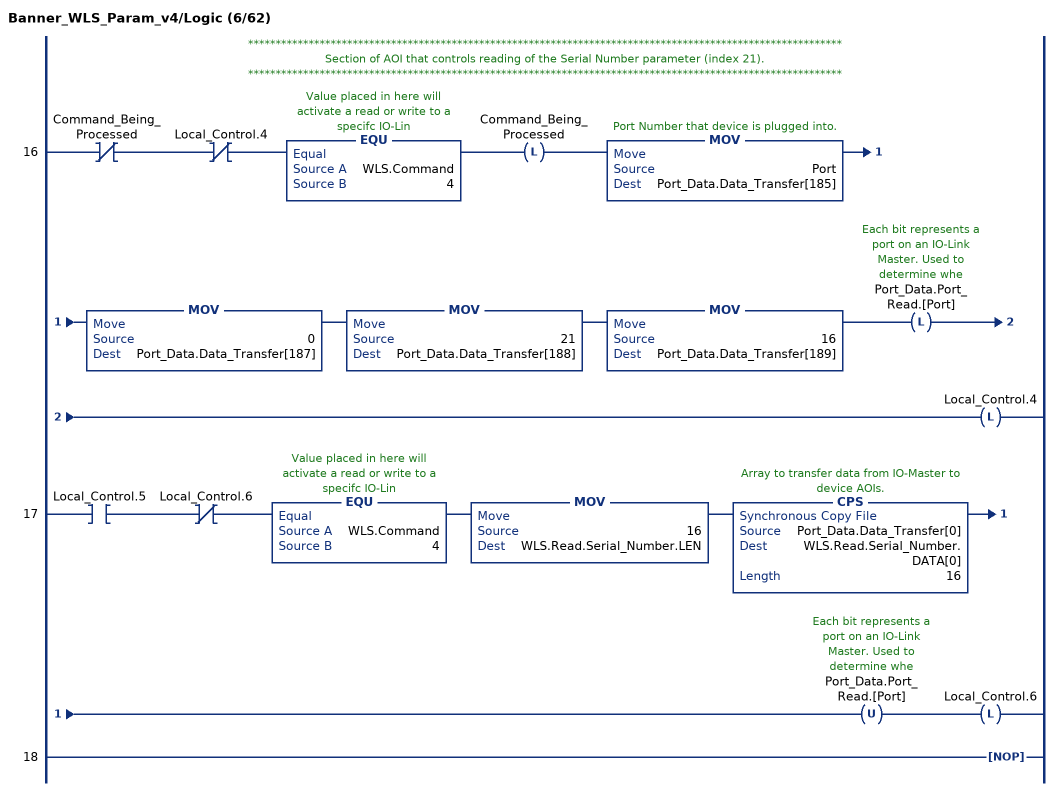
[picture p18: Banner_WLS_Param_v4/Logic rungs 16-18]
   // ************************************************************************************************************
   // Section of AOI that controls reading of the Serial Number parameter (index 21).
   // ************************************************************************************************************
   16: XIO(Command_Being_Processed)XIO(Local_Control.4)EQU(WLS.Command,4)OTL(Command_Being_Processed)MOV(Port,Port_Data.Data_Transfer[185])MOV(0,Port_Data.Data_Transfer[187])MOV(21,Port_Data.Data_Transfer[188])MOV(16,Port_Data.Data_Transfer[189])OTL(Port_Data.Port_Read.[Port])OTL(Local_Control.4);
   17: XIC(Local_Control.5)XIO(Local_Control.6)EQU(WLS.Command,4)MOV(16,WLS.Read.Serial_Number.LEN)CPS(Port_Data.Data_Transfer[0],WLS.Read.Serial_Number.DATA[0],16)OTU(Port_Data.Port_Read.[Port])OTL(Local_Control.6);
   18: NOP();
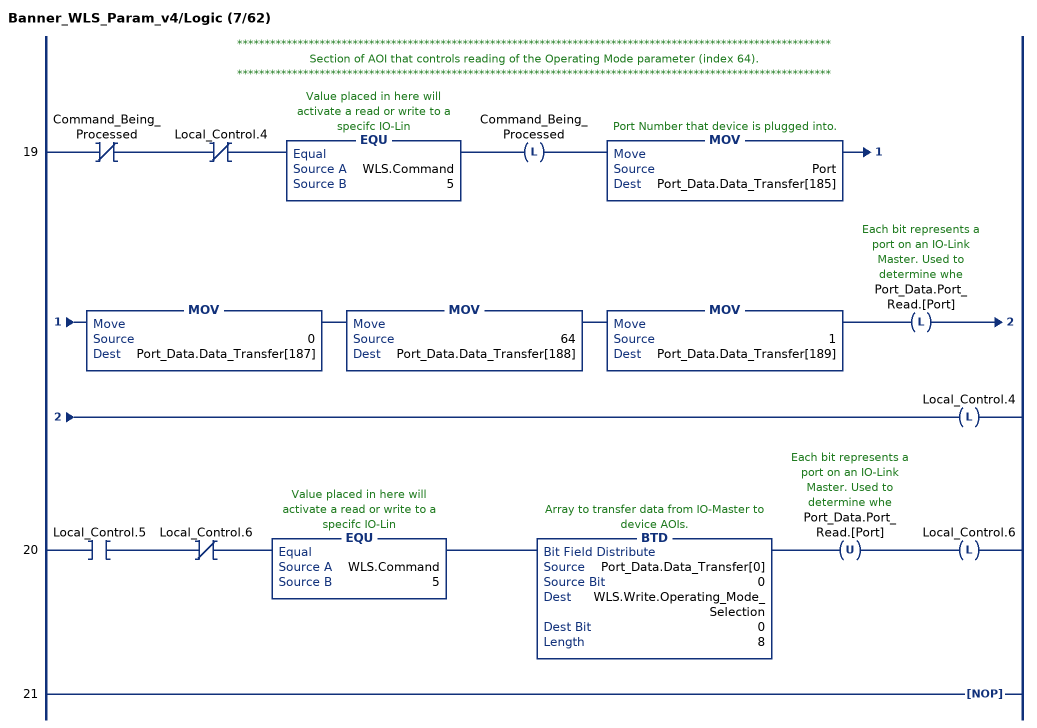
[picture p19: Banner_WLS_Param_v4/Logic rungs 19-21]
   // ************************************************************************************************************
   // Section of AOI that controls reading of the Operating Mode parameter (index 64).
   // ************************************************************************************************************
   19: XIO(Command_Being_Processed)XIO(Local_Control.4)EQU(WLS.Command,5)OTL(Command_Being_Processed)MOV(Port,Port_Data.Data_Transfer[185])MOV(0,Port_Data.Data_Transfer[187])MOV(64,Port_Data.Data_Transfer[188])MOV(1,Port_Data.Data_Transfer[189])OTL(Port_Data.Port_Read.[Port])OTL(Local_Control.4);
   20: XIC(Local_Control.5)XIO(Local_Control.6)EQU(WLS.Command,5)BTD(Port_Data.Data_Transfer[0],0,WLS.Write.Operating_Mode_Selection,0,8)OTU(Port_Data.Port_Read.[Port])OTL(Local_Control.6);
   21: NOP();
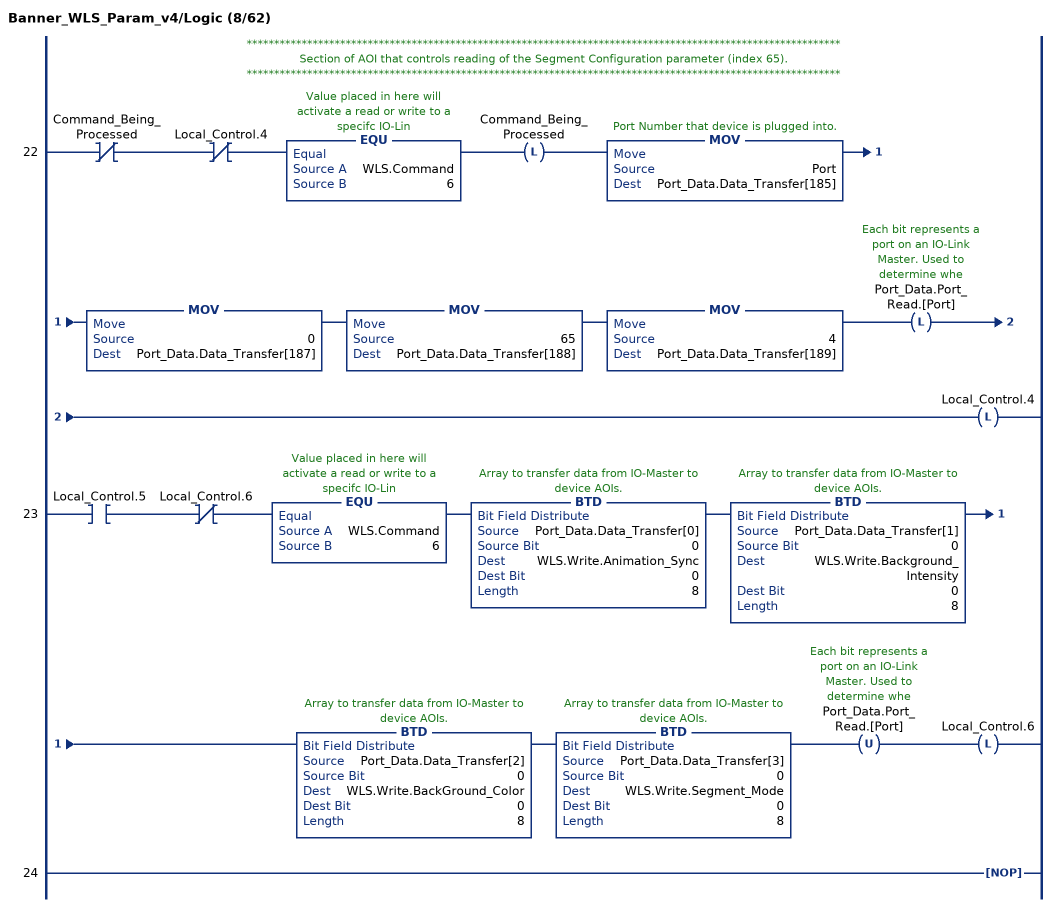
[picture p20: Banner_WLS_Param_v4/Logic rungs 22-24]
   // ************************************************************************************************************
   // Section of AOI that controls reading of the Segment Configuration parameter (index 65).
   // ************************************************************************************************************
   22: XIO(Command_Being_Processed)XIO(Local_Control.4)EQU(WLS.Command,6)OTL(Command_Being_Processed)MOV(Port,Port_Data.Data_Transfer[185])MOV(0,Port_Data.Data_Transfer[187])MOV(65,Port_Data.Data_Transfer[188])MOV(4,Port_Data.Data_Transfer[189])OTL(Port_Data.Port_Read.[Port])OTL(Local_Control.4);
   23: XIC(Local_Control.5)XIO(Local_Control.6)EQU(WLS.Command,6)BTD(Port_Data.Data_Transfer[0],0,WLS.Write.Animation_Sync,0,8)BTD(Port_Data.Data_Transfer[1],0,WLS.Write.Background_Intensity,0,8)BTD(Port_Data.Data_Transfer[2],0,WLS.Write.BackGround_Color,0,8)BTD(Port_Data.Data_Transfer[3],0,WLS.Write.Segment_Mode,0,8)OTU(Port_Data.Port_Read.[Port])OTL(Local_Control.6);
   24: NOP();
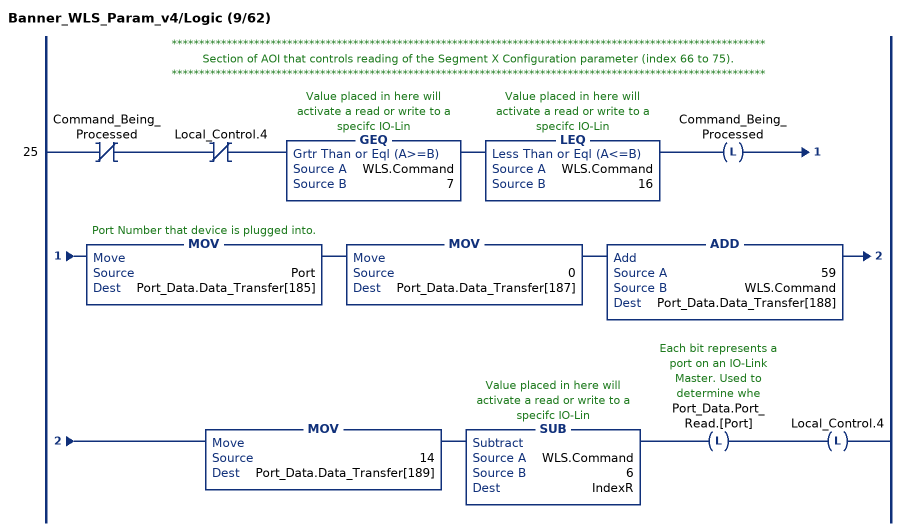
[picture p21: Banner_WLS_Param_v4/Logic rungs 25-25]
   // ************************************************************************************************************
   // Section of AOI that controls reading of the Segment X Configuration parameter (index 66 to 75).
   // ************************************************************************************************************
   25: XIO(Command_Being_Processed)XIO(Local_Control.4)GEQ(WLS.Command,7)LEQ(WLS.Command,16)OTL(Command_Being_Processed)MOV(Port,Port_Data.Data_Transfer[185])MOV(0,Port_Data.Data_Transfer[187])ADD(59,WLS.Command,Port_Data.Data_Transfer[188])MOV(14,Port_Data.Data_Transfer[189])SUB(WLS.Command,6,IndexR)OTL(Port_Data.Port_Read.[Port])OTL(Local_Control.4);
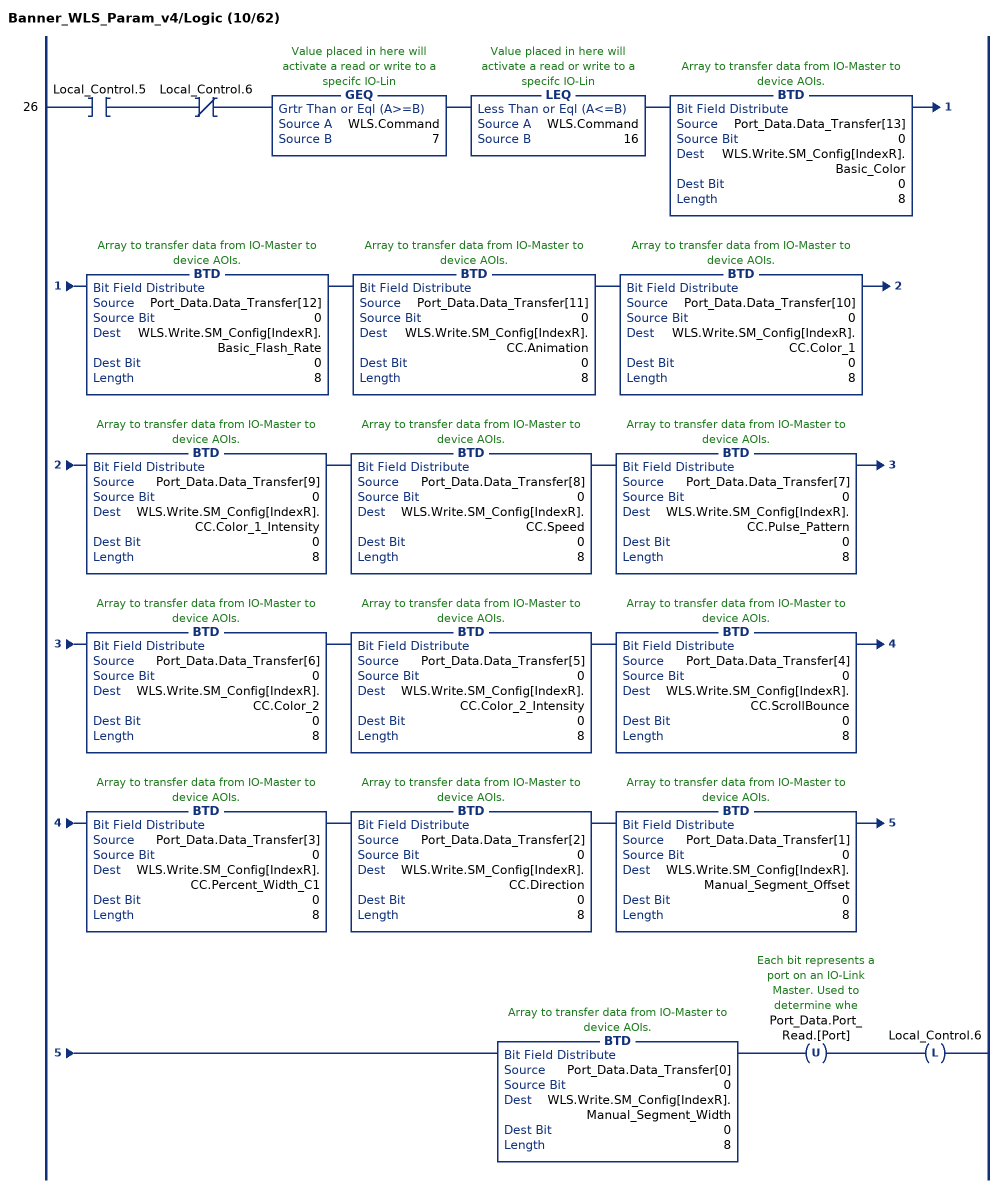
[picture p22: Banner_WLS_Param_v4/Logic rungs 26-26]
   26: XIC(Local_Control.5)XIO(Local_Control.6)GEQ(WLS.Command,7)LEQ(WLS.Command,16)BTD(Port_Data.Data_Transfer[13],0,WLS.Write.SM_Config[IndexR].Basic_Color,0,8)BTD(Port_Data.Data_Transfer[12],0,WLS.Write.SM_Config[IndexR].Basic_Flash_Rate,0,8)BTD(Port_Data.Data_Transfer[11],0,WLS.Write.SM_Config[IndexR].CC.Animation,0,8)BTD(Port_Data.Data_Transfer[10],0,WLS.Write.SM_Config[IndexR].CC.Color_1,0,8)BTD(Port_Data.Data_Transfer[9],0,WLS.Write.SM_Config[IndexR].CC.Color_1_Intensity,0,8)BTD(Port_Data.Data_Transfer[8],0,WLS.Write.SM_Config[IndexR].CC.Speed,0,8)BTD(Port_Data.Data_Transfer[7],0,WLS.Write.SM_Config[IndexR].CC.Pulse_Pattern,0,8)BTD(Port_Data.Data_Transfer[6],0,WLS.Write.SM_Config[IndexR].CC.Color_2,0,8)BTD(Port_Data.Data_Transfer[5],0,WLS.Write.SM_Config[IndexR].CC.Color_2_Intensity,0,8)BTD(Port_Data.Data_Transfer[4],0,WLS.Write.SM_Config[IndexR].CC.ScrollBounce,0,8)BTD(Port_Data.Data_Transfer[3],0,WLS.Write.SM_Config[IndexR].CC.Percent_Width_C1,0,8)BTD(Port_Data.Data_Transfer[2],0,WLS.Write.SM_Config[IndexR].CC.Direction,0,8)BTD(Port_Data.Data_Transfer[1],0,WLS.Write.SM_Config[IndexR].Manual_Segment_Offset,0,8)BTD(Port_Data.Data_Transfer[0],0,WLS.Write.SM_Config[IndexR].Manual_Segment_Width,0,8)OTU(Port_Data.Port_Read.[Port])OTL(Local_Control.6);
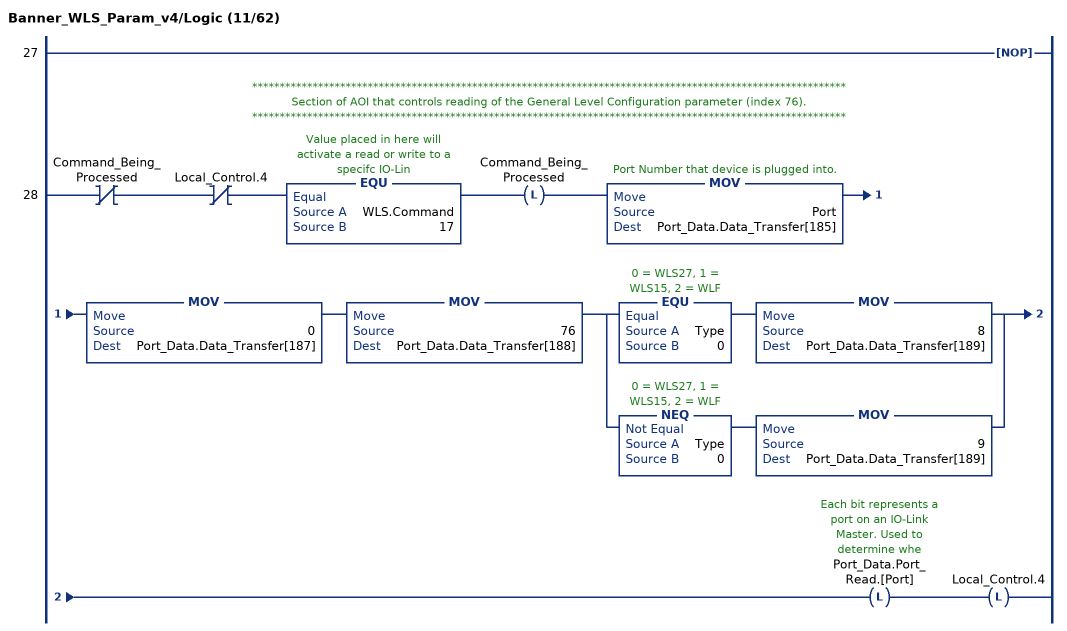
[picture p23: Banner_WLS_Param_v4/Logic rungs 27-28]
   27: NOP();
   // ************************************************************************************************************
   // Section of AOI that controls reading of the General Level Configuration parameter (index 76).
   // ************************************************************************************************************
   28: XIO(Command_Being_Processed)XIO(Local_Control.4)EQU(WLS.Command,17)OTL(Command_Being_Processed)MOV(Port,Port_Data.Data_Transfer[185])MOV(0,Port_Data.Data_Transfer[187])MOV(76,Port_Data.Data_Transfer[188])[EQU(Type,0) MOV(8,Port_Data.Data_Transfer[189]) ,NEQ(Type,0) MOV(9,Port_Data.Data_Transfer[189]) ]OTL(Port_Data.Port_Read.[Port])OTL(Local_Control.4);
